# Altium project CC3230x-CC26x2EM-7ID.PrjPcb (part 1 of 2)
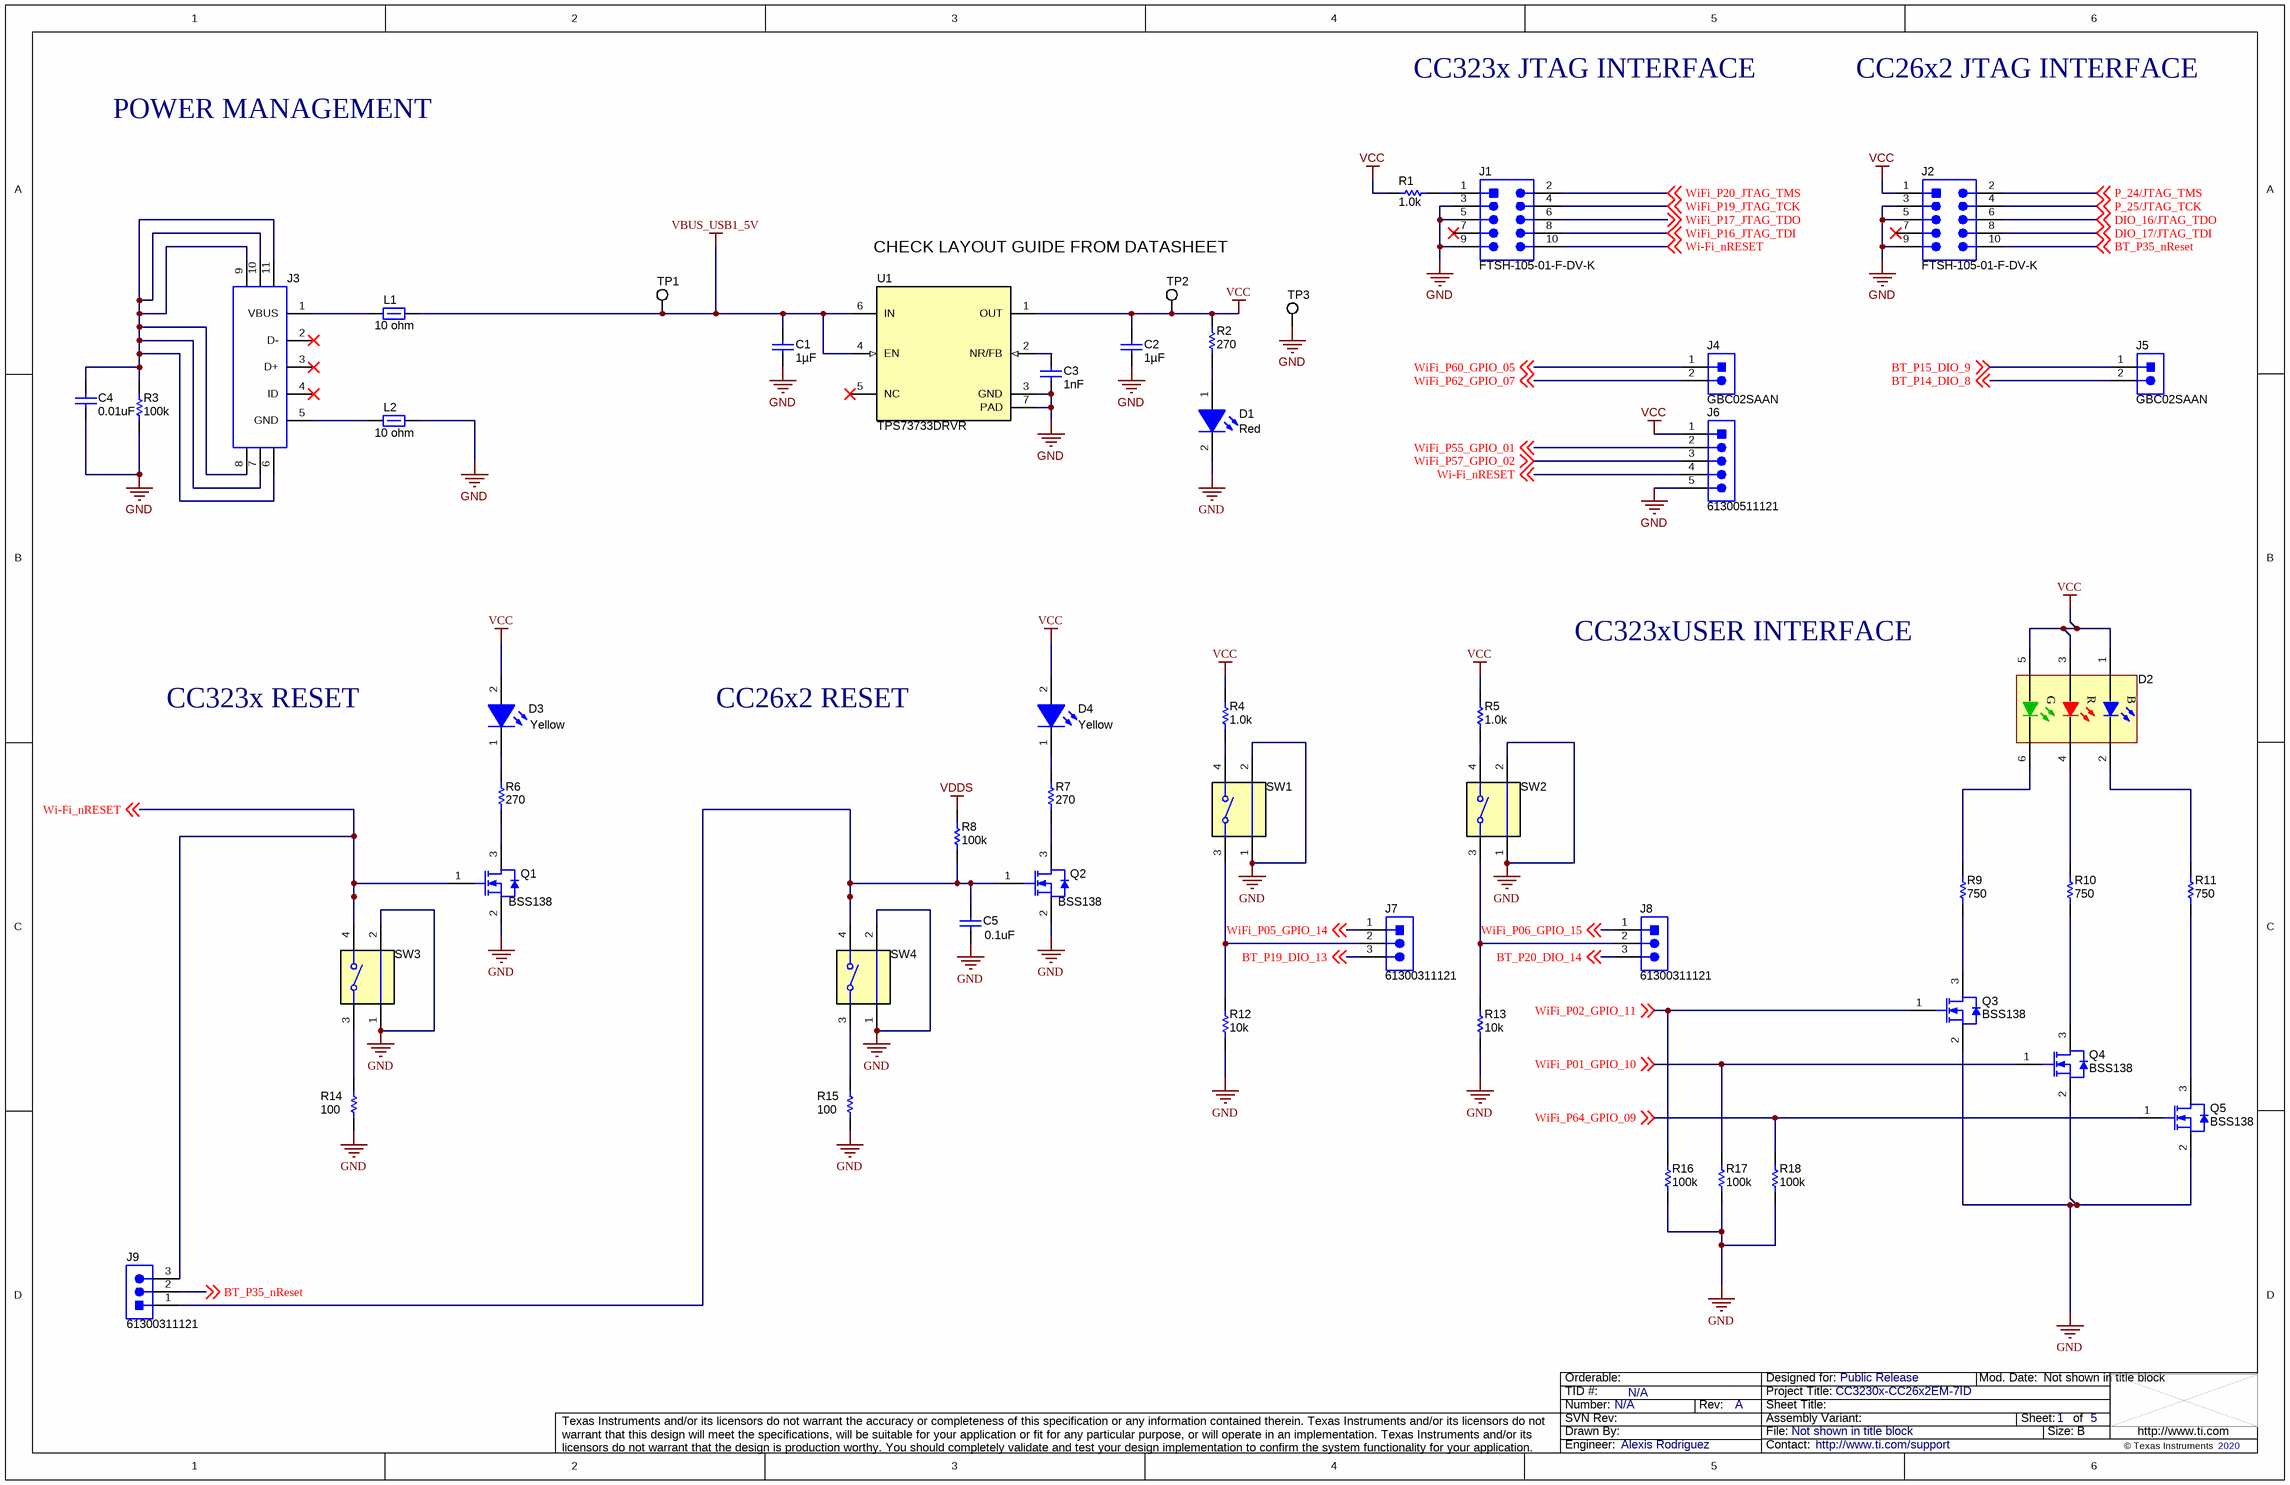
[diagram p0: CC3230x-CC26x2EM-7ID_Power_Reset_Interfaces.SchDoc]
CopyrightYear: 2020; PCB_Layout: Tessolve; PCB_Rev: A; PRJ_Customer: Public Release; PRJ_Engineer: Alexis Rodriguez; PRJ_Number: N/A; PRJ_Title: CC3230x-CC26x2EM-7ID; SCH_Rev: A; TechSupport: http://www.ti.com/support; TID: N/A
5 sheets, 160 parts. Net scope: global (net labels, ports and power ports of the same name join across sheets).
Board file: CC3230x-CC26x2EM-7ID.PcbDoc
Sheets:
  CC3230x-CC26x2EM-7ID_Power_Reset_Interfaces.SchDoc
  CC3230x-CC26x2EM-7ID_CC3230x_EngineArea.SchDoc
  CC3230x-CC26x2EM-7ID_CC26x2R_EngineArea.SchDoc
  CC3230x-CC26x2EM-7ID_AntennaRFSection.SchDoc
  CC3230x-CC26x2EM-7ID_Hardware.SchDoc

## Sheet CC3230x-CC26x2EM-7ID_Power_Reset_Interfaces.SchDoc
size 431 x 279 mm; Date: Not shown in title block; ApprovedBy: Not shown in title block; CheckedBy: Not shown in title block; Author: Not shown in title block; CompanyName: Not shown in title block; Engineer: Not shown in title block; Organization: Not shown in title block; Address1: Not shown in title block; Address2: Not shown in title block; Address3: Not shown in title block; Address4: Not shown in title block; DocumentNumber: 1; Revision: Use project parameter SCH_Rev; SheetNumber: 1; SheetTotal: 5; PageSetup: Record=PageOptions¦CenterHorizontal=True¦CenterVertical=True¦PrintScale=1.00¦XCorrection=1.00¦YCorrection=1.00¦PrintKind=0¦BorderSize=5000000¦LeftOffset=0¦BottomOffset=0¦Orientation=2¦PaperLength=1000¦PaperWidth=1000¦Scale=100¦PaperSource=15¦PrintQuality=600¦MediaType=1¦DitherType=10¦PaperKind=Letter¦PrintScaleMode=1

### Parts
C1  Cap_F: 1µF  [0603]  (hidden comment: GRM188R71E105KA12D)
C2  Cap_F: 1µF  [0603]  (hidden comment: GRM188R71E105KA12D)
C3  Cap_F: 1nF  [0603]  (hidden comment: 06031C102JAT2A)
C4  ValueDisplayed: 0.01uF  [0402]  (hidden comment: C1005X7R1C103K050BA)
C5  ValueDisplayed: 0.1uF  [0201]  (hidden comment: GRM033Z71C104KE14D)
D1  value Red  [19-217_R6C-AL1M2VY_3T_Red]  (hidden comment: 19-217/R6C-AL1M2VY/3T)
D2  EAST1616RGBA8  [EAST1616_RGB]  (value not drawn)
D3  value Yellow  [WL-SMCW_YELLOW]  (hidden comment: 150060YS75000)
D4  value Yellow  [WL-SMCW_YELLOW]  (hidden comment: 150060YS75000)
J1  FTSH-105-01-F-DV-K  [Samtec_FTSH-105-01-x-DV-K]
J2  FTSH-105-01-F-DV-K  [Samtec_FTSH-105-01-x-DV-K]
J3  1051640001  [Molex_1051640001]  (value not drawn)
J4  GBC02SAAN  [Sullins_Gxx02SAAN]
J5  GBC02SAAN  [Sullins_Gxx02SAAN]
J6  61300511121  [Wurth_61300511121]
J7  61300311121  [WURTH_61300311121]
J8  61300311121  [WURTH_61300311121]
J9  61300311121  [WURTH_61300311121]
L1  ValueDisplayed: 10 ohm  [0402]  (hidden comment: CMP-0003309-1)
L2  ValueDisplayed: 10 ohm  [0402]  (hidden comment: CMP-0003309-1)
Q1  PartNumber: BSS138  [SOT-23]  (hidden comment: CMP-0000755-1)
Q2  PartNumber: BSS138  [SOT-23]  (hidden comment: CMP-0000755-1)
Q3  BSS138  [SOT-23]
Q4  BSS138  [SOT-23]
Q5  BSS138  [SOT-23]
R1  ValueDisplayed: 1.0k  [0402]  (hidden comment: CRCW04021K00JNED)
R2  ValueDisplayed: 270  [0603]  (hidden comment: CMP-0025765-4)
R3  ValueDisplayed: 100k  [0603]  (hidden comment: CMP-0025698-4)
R4  ValueDisplayed: 1.0k  [0402]  (hidden comment: CMP-0026852-3)
R5  ValueDisplayed: 1.0k  [0402]  (hidden comment: CMP-0026852-3)
R6  ValueDisplayed: 270  [0603]  (hidden comment: CMP-0025765-4)
R7  ValueDisplayed: 270  [0603]  (hidden comment: CMP-0025765-4)
R8  ValueDisplayed: 100k  [0201]  (hidden comment: RC0201JR-7D100KL)
R9  ValueDisplayed: 750  [0603]  (hidden comment: RC0603JR-07750RL)
R10  ValueDisplayed: 750  [0603]  (hidden comment: RC0603JR-07750RL)
R11  ValueDisplayed: 750  [0603]  (hidden comment: RC0603JR-07750RL)
R12  ValueDisplayed: 10k  [0402]  (hidden comment: CMP-0026825-5)
R13  ValueDisplayed: 10k  [0402]  (hidden comment: CMP-0026825-5)
R14  ValueDisplayed: 100  [0402]  (hidden comment: CMP-0026656-1)
R15  ValueDisplayed: 100  [0402]  (hidden comment: CMP-0026656-1)
R16  ValueDisplayed: 100k  [0402]  (hidden comment: CMP-0026823-3)
R17  ValueDisplayed: 100k  [0402]  (hidden comment: CMP-0026823-3)
R18  ValueDisplayed: 100k  [0402]  (hidden comment: CMP-0026823-3)
SW1  CMP-0002328-1  [SW_1188E]  (value not drawn)
SW2  CMP-0002328-1  [SW_1188E]  (value not drawn)
SW3  CMP-0002328-1  [SW_1188E]  (value not drawn)
SW4  CMP-0002328-1  [SW_1188E]  (value not drawn)
TP1  5015  [Testpoint_Keystone_Miniature]  (value not drawn)
TP2  5015  [Testpoint_Keystone_Miniature]  (value not drawn)
TP3  5015  [Testpoint_Keystone_Miniature]  (value not drawn)
U1  TPS73733DRVR  [DRV0006A]

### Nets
GND: C1.2 C2.2 C3.2 C4.2 C5.2 D1.2(K) J1.3 J1.5 J1.9 J2.3 J2.5 J2.9 J6.5 L2.2 Q1.2(S) Q2.2(S) Q3.2(S) Q4.2(S) Q5.2(S) R3.1 R12.2 R13.2 R14.1 R15.1 R16.2 R17.2 R18.2 SW1.1 SW1.2 SW2.1 SW2.2 SW3.1 SW3.2 SW4.1 SW4.2 TP3.1 U1.3(GND) U1.7(PAD)
VBUS_USB1_5V: C1.1 L1.2 TP1.1 U1.4(EN) U1.6(IN)
VCC: C2.1 D2.1(A) D2.3(A) D2.5(A) D3.2(A) D4.2(A) J2.1 J6.1 R1.1 R2.1 R4.1 R5.1 TP2.1 U1.1(OUT)
VDDS: R8.2
BT_P14_DIO_8: J5.2 ; off-sheet BT_P14_DIO_8
BT_P15_DIO_9: J5.1 ; off-sheet BT_P15_DIO_9
BT_P19_DIO_13: J7.3 ; off-sheet BT_P19_DIO_13
BT_P20_DIO_14: J8.3 ; off-sheet BT_P20_DIO_14
BT_P35_nReset: J2.10 J9.2 ; off-sheet BT_P35_nReset
DIO_16/JTAG_TDO: J2.6 ; off-sheet DIO_16/JTAG_TDO
DIO_17/JTAG_TDI: J2.8 ; off-sheet DIO_17/JTAG_TDI
P_24/JTAG_TMS: J2.2 ; off-sheet P_24/JTAG_TMS
P_25/JTAG_TCK: J2.4 ; off-sheet P_25/JTAG_TCK
Wi-Fi_nRESET: J1.10 J6.4 J9.3 Q1.1(G) SW3.4 ; off-sheet Wi-Fi_nRESET
WiFi_P01_GPIO_10: Q4.1(G) R17.1 ; off-sheet WiFi_P01_GPIO_10
WiFi_P02_GPIO_11: Q3.1(G) R16.1 ; off-sheet WiFi_P02_GPIO_11
WiFi_P05_GPIO_14: J7.1 ; off-sheet WiFi_P05_GPIO_14
WiFi_P06_GPIO_15: J8.1 ; off-sheet WiFi_P06_GPIO_15
WiFi_P16_JTAG_TDI: J1.8 ; off-sheet WiFi_P16_JTAG_TDI
WiFi_P17_JTAG_TDO: J1.6 ; off-sheet WiFi_P17_JTAG_TDO
WiFi_P19_JTAG_TCK: J1.4 ; off-sheet WiFi_P19_JTAG_TCK
WiFi_P20_JTAG_TMS: J1.2 ; off-sheet WiFi_P20_JTAG_TMS
WiFi_P55_GPIO_01: J6.2 ; off-sheet WiFi_P55_GPIO_01
WiFi_P57_GPIO_02: J6.3 ; off-sheet WiFi_P57_GPIO_02
WiFi_P60_GPIO_05: J4.1 ; off-sheet WiFi_P60_GPIO_05
WiFi_P62_GPIO_07: J4.2 ; off-sheet WiFi_P62_GPIO_07
WiFi_P64_GPIO_09: Q5.1(G) R18.1 ; off-sheet WiFi_P64_GPIO_09
NetC3_1: C3.1 U1.2(NR/FB)
NetC4_1: C4.1 J3.6 J3.7 J3.8 J3.9 J3.10 J3.11 R3.2
NetC5_1: C5.1 J9.1 Q2.1(G) R8.1 SW4.4
NetD1_1: D1.1(A) R2.2
NetD2_2: D2.2(K) R11.2
NetD2_4: D2.4(K) R10.2
NetD2_6: D2.6(K) R9.2
NetD3_1: D3.1(K) R6.2
NetD4_1: D4.1(K) R7.2
NetJ1_1: J1.1 R1.2
NetJ3_1: J3.1(VBUS) L1.1
NetJ3_5: J3.5(GND) L2.1
NetJ7_2: J7.2 R12.1 SW1.3
NetJ8_2: J8.2 R13.1 SW2.3
NetQ1_3: Q1.3(D) R6.1
NetQ2_3: Q2.3(D) R7.1
NetQ3_3: Q3.3(D) R9.1
NetQ4_3: Q4.3(D) R10.1
NetQ5_3: Q5.3(D) R11.1
NetR4_2: R4.2 SW1.4
NetR5_2: R5.2 SW2.4
NetR14_2: R14.2 SW3.3
NetR15_2: R15.2 SW4.3

Not connected (* = marked no-connect by the designer): J1 7*; J2 7*; J3 2(D-)* 3(D+)* 4(ID)*; U1 5(NC)*

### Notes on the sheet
- CC323x JTAG INTERFACE
- CC26x2 JTAG INTERFACE
- POWER MANAGEMENT
- CHECK LAYOUT GUIDE FROM DATASHEET
- CC323xUSER INTERFACE
- CC323x RESET
- CC26x2 RESET

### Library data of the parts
C1 C2 = CMP-0007405-4: CAP, CERM, 1 uF, 25 V, +/- 10%, X7R, 0603; Manufacturer: MuRata; TaMin_C: -55°C; Polarized: N; SizeAreaWB_mm2: 4.68; Value1: Unknown; U/M: EA; Value: 1uF; TaMax_C: 125°C; SizeZ_mm: 1; SizeX_mm: 1.6; SizeY_mm: 0.8; Value2: 25V; SizeArea_mm2: 1.28; CompType: Capacitor; AEC Category: Q200
C3 = CMP-0006723-4: CAP, CERM, 1000 pF, 100 V, +/- 5%, X7R, 0603; Manufacturer: AVX; TaMin_C: -55°C; ESR_ohm: 2.76d; Polarized: N; SizeAreaWB_mm2: 4.68; Value1: 0.276 ohm; U/M: EA; Value: 1000pF; TaMax_C: 125°C; SizeZ_mm: 1; SizeX_mm: 1.6; SizeY_mm: 0.8; Value2: 100V; SizeArea_mm2: 1.28; CompType: Capacitor; AEC Category: Q200
C4 = CMP-0006292-2: CAP, CERM, 0.01 uF, 16 V, +/- 10%, X7R, 0402; Manufacturer: TDK; Alternate PartNumber: 0402B103K500CT; Alternate Manufacturer: Walsin; Polarized: N; CompType: Capacitor; Value: 0.01uF; U/M: EA; Cap_F: 10nF; ESR_ohm: 0.0623; Value1: 0.0623 ohm; VDC_V: 16V; TaMin_C: -55°C; TaMax_C: 125°C; AEC Category: Q200; SizeAreaWB_mm2: 3; SizeZ_mm: 0.6; SizeX_mm: 1; SizeY_mm: 0.5
C5 = CMP-0064970-1: CAP, CERM, 0.1 uF, 16 V,+/- 10%, X7R, 0201; Manufacturer: MuRata; TaMin_C: -55°C; Polarized: N; SizeAreaWB_mm2: 2.08; Value1: Unknown; U/M: EA; Value: 0.1uF; TaMax_C: 125°C; SizeZ_mm: 0.26; SizeX_mm: 0.6; SizeY_mm: 0.3; Value2: 16V; SizeArea_mm2: 0.18; CompType: Capacitor; Cap_F: 100nF; AEC Category: Q200
D1 = CMP-0086159-1: LED, Red, SMD; Manufacturer: Everlight; SizeArea_mm2: 1.28; Tjmax_C: 85°C; Angle: 120; SizeZ_mm: 0.5; Value1: 0.06W; Ir_A: 10µA; SizeX_mm: 1.6; Io_A: 5mA; Vf_V: 1.95V; SizeY_mm: 0.8; Vr_V: 5V; Power_TotalModule: 60mW; SizeAreaWB_mm2: 4.68
D2 = CMP-0003017-3: LED, RGB, SMD; Manufacturer: Everlight; SizeZ_mm: 0.45; Io_A: 25mA; SizeY_mm: 1.6; Type: InGaN; Ir_A: 50µA; Vr_V: 5V; Value2: 3.7V; SizeAreaWB_mm2: 6.76; SizeArea_mm2: 2.56; Angle: 120; Tjmax_C: 85°C
D3 D4 = CMP-0002892-3: LED, Yellow, SMD; Manufacturer: Wurth Elektronik; Value1: W; Vf_V: 2V; Type: AlInGaP; Io_A: 20mA
J1 J2 = CMP-0075670-2: Header (Shrouded), 1.27mm, 5x2, Gold, SMT; Manufacturer: Samtec; Pitch_mm: 1.27; Gender: Male; Cert_CSA: Y; Current_A: 3.3A; Row_Count: 2
J3 = CMP-0055311-1: Receptacle, USB 2.0, Micro B, 5 Position, R/A, SMT; Manufacturer: Molex; CNHeader: FALSE; Current_A: 1.8A; Gender: Female; Voltage_V: 30V; Pitch_mm: 0.65; ContactFinish: Gold; CT: TRUE; Cert_UL: Y
J4 J5 = CMP-0054576-1: Header, 2.54 mm, 2x1, Gold, TH; Manufacturer: Sullins Connector Solutions; CT: FALSE; CNHeader: TRUE
J6 = CMP-0084909-1: Header, 2.54mm, 5x1, Gold, TH; Manufacturer: Wurth Elektronik; Pitch_mm: 2.54; Gender: Male; Row_Count: 1; Shrouded: N; Current_A: 3A; Voltage_V: 250V
J7-J9 = CMP-0054796-2: Header, 2.54 mm, 3x1, Gold, TH; Manufacturer: Wurth Elektronik; Pitch_mm: 2.54; Green_Lifecycle: Active; Cert_UL: Y; Shrouded: N; Green_REACh: Passed; Gender: Male; Row_Count: 1
L1 L2 = CMP-0003309-1: Ferrite Bead, 10 ohm @ 100 MHz, 1 A, 0402; PartNumber: BLM15AG100SN1D; Manufacturer: MuRata; Alternate PartNumber: ----; Value: 10 ohm; Imax_A: 1A; DCR_ohm: 0.025; Value1: 0.025 ohm; ZTyp@100MHz_Ohm: 10; SizeAreaWB_mm2: 3; SizeZ_mm: 0.6; SizeX_mm: 1; SizeY_mm: 0.5
Q1 Q2 = CMP-0000755-1: MOSFET, N-CH, 50 V, 0.22 A, SOT-23; Manufacturer: Fairchild Semiconductor; Alternate Manufacturer: ON; Alternate PartNumber: BSS138LT1G; U/M: EA; ChType: N; Value: 50V; Rdson45_ohm: 6; Value2: 1.7 nC; QgTyp_nC: 1.7; Vgs_V: 20V; IdsMax_A: 2.2dA; SizeZ_mm: 1.1; SizeX_mm: 2.5; SizeY_mm: 3; SizeArea_mm2: 7.5; AEC Category: Q101; SizeAreaWB_mm2: 14
Q3-Q5 = CMP-0000755-1: MOSFET, N-CH, 50 V, 0.22 A, SOT-23; Alternate Manufacturer: None; Manufacturer: Fairchild Semiconductor; SizeZ_mm: 1.1; ChType: N; Value2: 1.7 nC; VdsMax_V: 50V; SizeX_mm: 2.5; SizeY_mm: 3; Vgs_V: 20V; Value: 50V; Rdson45_ohm: 6; SizeArea_mm2: 7.5; AEC Category: Q101; IdsMax_A: 2.2dA; SizeAreaWB_mm2: 14; U/M: EA; QgTyp_nC: 1.7
R1 = CMP-0026852-3: RES, 1.0 k, 5%, 0.063 W, AEC-Q200 Grade 0, 0402; Manufacturer: Vishay-Dale; Power_W: 63mW; TempCo: 200 ppm/C; Value_Code: 1k00; Value: 1.0k; EIA_Code: E24; Res_ohm: 1k; SizeX_mm: 1; SizeY_mm: 0.5; SizeZ_mm: 0.6; Value2: 0.063W; AEC Qualified: Y; VDC_V: 50V; AEC Category: Q200; AEC Grade: 0
R2 = CMP-0025765-4: RES, 270, 5%, 0.1 W, AEC-Q200 Grade 0, 0603; PartNumber: CRCW0603270RJNEA; Manufacturer: Vishay-Dale; Alternate Manufacturer: YAGEO; Alternate PartNumber: RC0603JR-07270RL; Value: 270; Value_Code: 270R; Power_W: 100mW; Value2: 0.1W; VDC_V: 75V; TempCo: 200 ppm/C; EIA_Code: E24; SizeX_mm: 1.6; SizeY_mm: 0.8; SizeZ_mm: 1; SizeArea_mm2: 1.28; AEC Qualified: Y; AEC Category: Q200; AEC Grade: 0
R3 = CMP-0025698-4: RES, 100 k, 5%, 0.1 W, AEC-Q200 Grade 0, 0603; PartNumber: CRCW0603100KJNEA; Manufacturer: Vishay-Dale; Alternate Manufacturer: YAGEO; Alternate PartNumber: RC0603JR-07100KL; CompType: Resistor; Value: 100k; Power_W: 100mW; Value2: 0.1W; VDC_V: 75V; TempCo: 200 ppm/C; EIA_Code: E24; AEC Category: Q200; AEC Qualified: Y; AEC Grade: 0; SizeX_mm: 1.6; SizeY_mm: 0.8; SizeZ_mm: 1; SizeArea_mm2: 1.28
R4 R5 = CMP-0026852-3: RES, 1.0 k, 5%, 0.063 W, AEC-Q200 Grade 0, 0402; PartNumber: CRCW04021K00JNED; Manufacturer: Vishay-Dale; Alternate Manufacturer: YAGEO; Alternate PartNumber: RC0402JR-071KL; Value: 1.0k; Res_ohm: 1k; Value_Code: 1k00; Power_W: 63mW; Value2: 0.063W; VDC_V: 50V; TempCo: 200 ppm/C; EIA_Code: E24; SizeX_mm: 1; SizeY_mm: 0.5; SizeZ_mm: 0.6; AEC Qualified: Y; AEC Category: Q200; AEC Grade: 0
R6 R7 = CMP-0025765-4: RES, 270, 5%, 0.1 W, AEC-Q200 Grade 0, 0603; PartNumber: CRCW0603270RJNEA; Manufacturer: Vishay-Dale; Alternate Manufacturer: YAGEO; Alternate PartNumber: RC0603JR-07270RL; CompType: Resistor; Value: 270; Value_Code: 270R; Power_W: 100mW; Value2: 0.1W; VDC_V: 75V; TempCo: 200 ppm/C; EIA_Code: E24; SizeX_mm: 1.6; SizeY_mm: 0.8; SizeZ_mm: 1; SizeArea_mm2: 1.28; AEC Qualified: Y; AEC Category: Q200; AEC Grade: 0
R8 = CMP-0027184-1: RES, 100 k, 5%, 0.05 W, 0201; Manufacturer: Yageo America; Power_W: 50mW; TempCo: 200 ppm/C; U/M: EA; Value: 100k; EIA_Code: E24; SizeX_mm: 0.6; SizeY_mm: 0.3; SizeZ_mm: 0.26; Value2: 0.05W; SizeArea_mm2: 0.18; CompType: Resistor; AEC Qualified: N; VDC_V: 25V; AEC Category: Q200
R9-R11 = CMP-0025939-5: RES, 750, 5%, 0.1 W, 0603; Manufacturer: Yageo; Power_W: 100mW; TempCo: 100 ppm/C; Value_Code: 750R; Value: 750; EIA_Code: E24; SizeX_mm: 1.6; SizeY_mm: 0.8; SizeZ_mm: 1; Value2: 0.1W; SizeArea_mm2: 1.28; AEC Qualified: N; VDC_V: 75V; AEC Category: Q200; SizeAreaWB_mm2: 4.68
R12 R13 = CMP-0026825-5: RES, 10 k, 5%, 0.063 W, AEC-Q200 Grade 0, 0402; PartNumber: CRCW040210K0JNED; Manufacturer: Vishay-Dale; Alternate Manufacturer: YAGEO; Alternate PartNumber: RC0402JR-0710KL; Value: 10k; Value_Code: 10k0; Power_W: 63mW; Value2: 0.063W; VDC_V: 50V; TempCo: 200 ppm/C; EIA_Code: E24; SizeX_mm: 1; SizeY_mm: 0.5; SizeZ_mm: 0.6; AEC Qualified: Y; AEC Category: Q200; AEC Grade: 0
R14 R15 = CMP-0026656-1: RES, 100, 1%, 0.1 W, 0402; PartNumber: ERJ-2RKF1000X; Manufacturer: Panasonic; Alternate Manufacturer: YAGEO; Alternate PartNumber: RC0402FR-07100RL; CompType: Resistor; Value: 100; Value_Code: 100R; Power_W: 100mW; Value2: 0.1W; VDC_V: 50V; TempCo: 100 ppm/C; EIA_Code: E96; U/M: EA; SizeX_mm: 1; SizeY_mm: 0.5; SizeZ_mm: 0.6; AEC Category: Q200
R16-R18 = CMP-0026823-3: RES, 100 k, 5%, 0.063 W, AEC-Q200 Grade 0, 0402; PartNumber: CRCW0402100KJNED; Manufacturer: Vishay-Dale; Alternate Manufacturer: YAGEO; Alternate PartNumber: RC0402JR-07100KL; Value: 100k; Power_W: 63mW; Value2: 0.063W; VDC_V: 50V; TempCo: 200 ppm/C; EIA_Code: E24; SizeArea_mm2: 0.5; SizeX_mm: 1; SizeZ_mm: 0.6; AEC Category: Q200; AEC Qualified: Y; AEC Grade: 0
SW1-SW4 = CMP-0002328-1: Switch, SPST, 0.05 A, 12 VDC, SMD; PartNumber: 1188E-1K2-V-TR; Manufacturer: Diptronics; Alternate Manufacturer: ----; VDC_V: 12V; PositionCount: 1; CurrentRating_mA: 50A; SizeAreaWB_mm2: 53.9; SizeArea_mm2: 27.3; SizeX_mm: 7.8; SizeY_mm: 3.5
TP1-TP3 = CMP-0055152-1: Test Point, Miniature, SMT; Manufacturer: Keystone; CNHeader: FALSE; Green_Lifecycle: Active; Green_REACh: Passed; CT: TRUE
U1 = CMP-0073832-5: Single Output LDO, 1A, Adj. (1.2 to 5.0V), Reverse Current Protection, DRV0006A (WSON-6); Manufacturer: Texas Instruments; Alternate PartNumber: TPS73733DRVT; SizeX_mm: 2; CompType: IC; SizeZ_mm: 0.8; SizeArea_mm2: 4; SizeAreaWB_mm2: 9; Green_Lifecycle: Active; Green_REACh: Passed; AEC Category: Q200; AEC Qualified: N; Rating: Catalog

## Sheet CC3230x-CC26x2EM-7ID_CC3230x_EngineArea.SchDoc
size 558 x 431 mm; Date: Not shown in title block; ApprovedBy: Not shown in title block; CheckedBy: Not shown in title block; Author: Not shown in title block; CompanyName: Not shown in title block; Engineer: Not shown in title block; Organization: Not shown in title block; Address1: Not shown in title block; Address2: Not shown in title block; Address3: Not shown in title block; Address4: Not shown in title block; DocumentNumber: 2; Revision: Use project parameter SCH_Rev; SheetNumber: 2; SheetTotal: 5; PageSetup: Record=PageOptions¦CenterHorizontal=True¦CenterVertical=True¦PrintScale=1.00¦XCorrection=1.00¦YCorrection=1.00¦PrintKind=0¦BorderSize=5000000¦LeftOffset=0¦BottomOffset=0¦Orientation=2¦PaperLength=1000¦PaperWidth=1000¦Scale=100¦PaperSource=15¦PrintQuality=600¦MediaType=1¦DitherType=10¦PaperKind=Letter¦PrintScaleMode=1
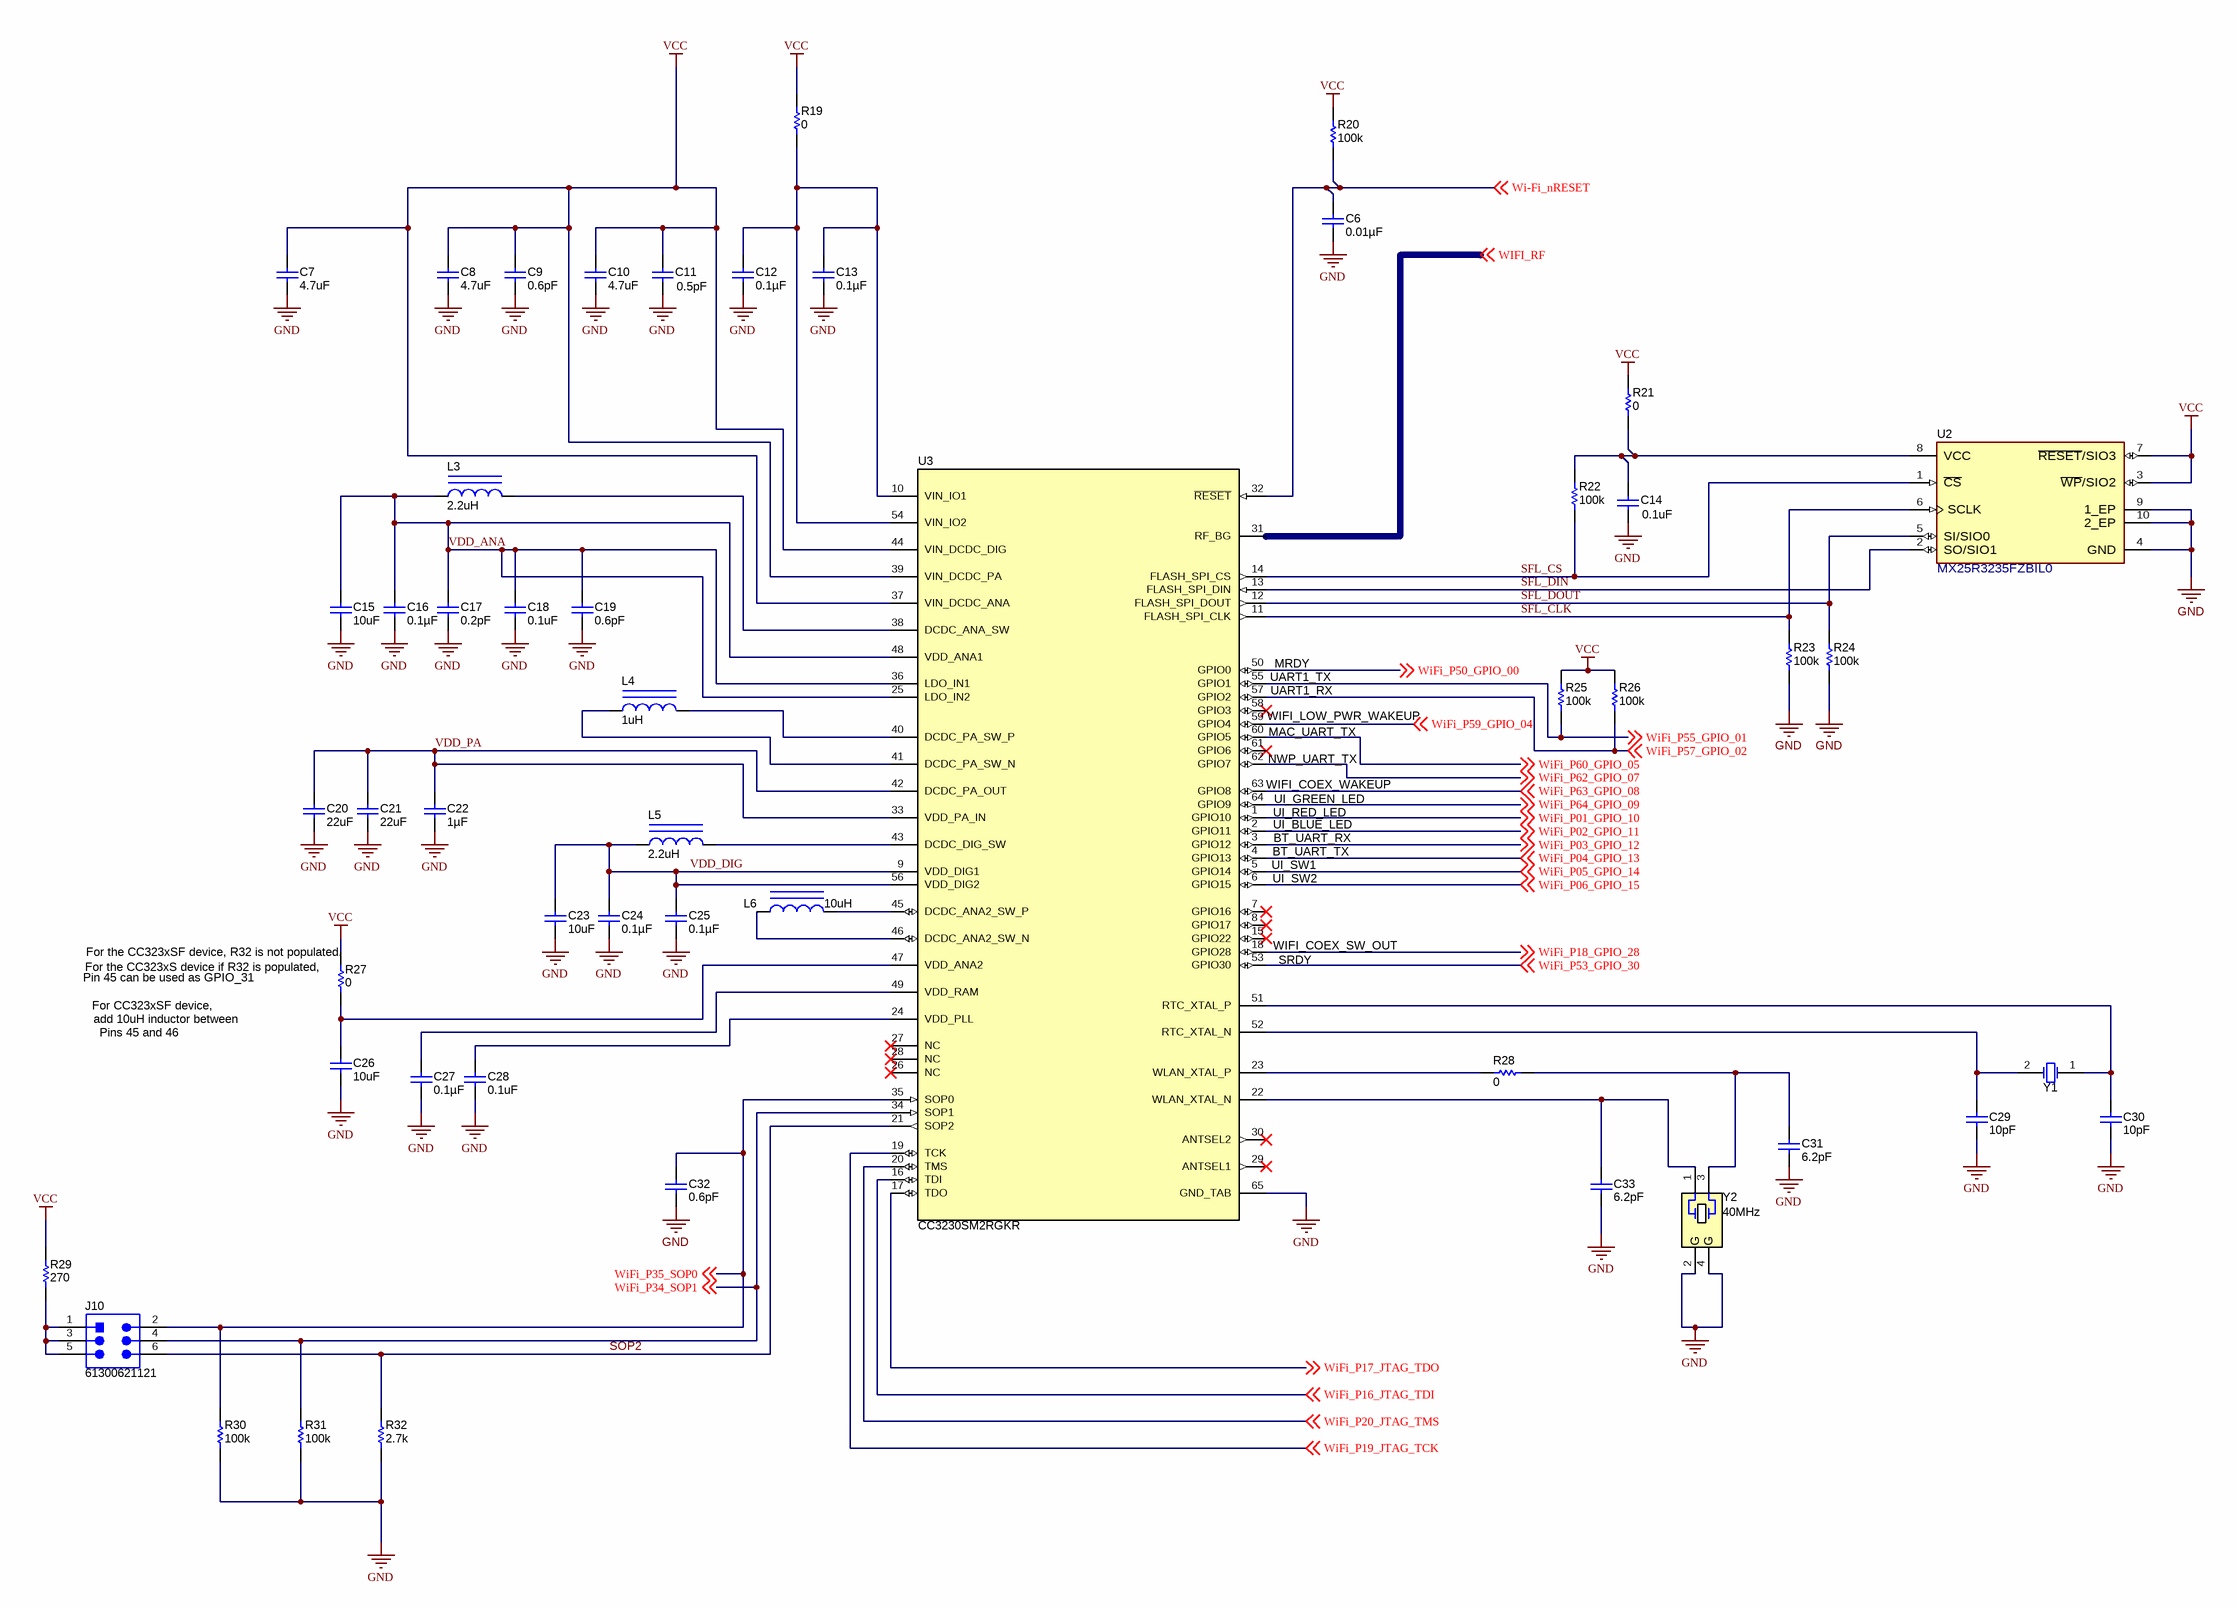
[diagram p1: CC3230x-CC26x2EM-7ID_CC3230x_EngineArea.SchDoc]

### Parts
C6  ValueDisplayed: 0.01µF  [0402S]  (hidden comment: 0402B103K500CT)
C7  ValueDisplayed: 4.7uF  [0402]  (hidden comment: CMP-0064972-2)
C8  ValueDisplayed: 4.7uF  [0402]  (hidden comment: CMP-0064972-2)
C9  ValueDisplayed: 0.6pF  [0201_033]  (hidden comment: GJM0335C1ER60BB01D)
C10  ValueDisplayed: 4.7uF  [0402]  (hidden comment: CMP-0064972-2)
C11  ValueDisplayed: 0.5pF  [0201_033]  (hidden comment: GJM0335C1ER50BB01D)
C12  ValueDisplayed: 0.1µF  [0402S]  (hidden comment: CL05B104KO5NNNC)
C13  ValueDisplayed: 0.1µF  [0402S]  (hidden comment: CL05B104KO5NNNC)
C14  ValueDisplayed: 0.1uF  [0201]  (hidden comment: GRM033Z71C104KE14D)
C15  ValueDisplayed: 10uF  [0603]  (hidden comment: CMP-0064953-4)
C16  ValueDisplayed: 0.1µF  [0402S]  (hidden comment: CL05B104KO5NNNC)
C17  ValueDisplayed: 0.2pF  [0201_033]  (hidden comment: GJM0335C1ER20BB01D)
C18  ValueDisplayed: 0.1uF  [0201]  (hidden comment: CL03A104KP3NNNC)
C19  ValueDisplayed: 0.6pF  [0201_033]  (hidden comment: GJM0335C1ER60BB01D)
C20  ValueDisplayed: 22uF  [0603]  (hidden comment: CMP-0064952-4)
C21  ValueDisplayed: 22uF  [0603]  (hidden comment: CMP-0064952-4)
C22  ValueDisplayed: 1µF  [0402S]  (hidden comment: CL05A105MP5NNNC)
C23  ValueDisplayed: 10uF  [0603]  (hidden comment: CMP-0064953-4)
C24  ValueDisplayed: 0.1µF  [0402S]  (hidden comment: CL05B104KO5NNNC)
C25  ValueDisplayed: 0.1µF  [0402S]  (hidden comment: CL05B104KO5NNNC)
C26  ValueDisplayed: 10uF  [0603]  (hidden comment: CMP-0064953-4)
C27  ValueDisplayed: 0.1µF  [0402S]  (hidden comment: CL05B104KO5NNNC)
C28  ValueDisplayed: 0.1uF  [0201]  (hidden comment: CMP-0009655-3)
C29  ValueDisplayed: 10pF  [0402S]  (hidden comment: 0402N100J500CT)
C30  ValueDisplayed: 10pF  [0402S]  (hidden comment: 0402N100J500CT)
C31  ValueDisplayed: 6.2pF  [0402S]  (hidden comment: 0402N6R2C500CT)
C32  ValueDisplayed: 0.6pF  [0201_033]  (hidden comment: GJM0335C1ER60BB01D)
C33  ValueDisplayed: 6.2pF  [0402S]  (hidden comment: 0402N6R2C500CT)
J10  61300621121  [Wurth_61300621121]
L3  ValueDisplayed: 2.2uH  [LQM2MPN_G0]  (hidden comment: CMP-0058761-1)
L4  ValueDisplayed: 1uH  [1008]  (hidden comment: CMP-0058750-1)
L5  ValueDisplayed: 2.2uH  [LQM2MPN_G0]  (hidden comment: CMP-0058761-1)
L6  ValueDisplayed: 10uH  [MLP2520S-M]  (hidden comment: CMP-0062710-1)
R19  ValueDisplayed: 0  [0201]  (hidden comment: CRCW02010000Z0ED)
R20  ValueDisplayed: 100k  [0402]  (hidden comment: CRCW0402100KJNED)
R21  ValueDisplayed: 0  [0201]  (hidden comment: CRCW02010000Z0ED)
R22  ValueDisplayed: 100k  [0201]  (hidden comment: RC0201JR-7D100KL)
R23  ValueDisplayed: 100k  [0201]  (hidden comment: RC0201JR-7D100KL)
R24  ValueDisplayed: 100k  [0201]  (hidden comment: RC0201JR-7D100KL)
R25  ValueDisplayed: 100k  [0201]  (hidden comment: RC0201JR-7D100KL)
R26  ValueDisplayed: 100k  [0201]  (hidden comment: RC0201JR-7D100KL)
R27  ValueDisplayed: 0  [0201]  (hidden comment: CRCW02010000Z0ED)
R28  ValueDisplayed: 0  [0201]  (hidden comment: CRCW02010000Z0ED)
R29  ValueDisplayed: 270  [0402]  (hidden comment: CRCW0402270RJNED)
R30  ValueDisplayed: 100k  [0402]  (hidden comment: CRCW0402100KJNED)
R31  ValueDisplayed: 100k  [0402]  (hidden comment: CRCW0402100KJNED)
R32  ValueDisplayed: 2.7k  [0402]  (hidden comment: CRCW04022K70JNED)
U2  MX25R3235FZBIL0  [FP-MX25R3235FZBIL0_USON8-MFG]
U3  CC3230SM2RGKR  [RGK0064B]
Y1  CMP-0004575-3  [XTAL_ABS07]  (value not drawn)
Y2  Frequency_Fixed: 40MHz  [TXC_8Y]  (hidden comment: 8Y40072002)

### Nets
GND: C6.2 C7.2 C8.2 C9.2 C10.2 C11.2 C12.2 C13.2 C14.2 C15.2 C16.2 C17.2 C18.2 C19.2 C20.2 C21.2 C22.2 C23.2 C24.2 C25.2 C26.2 C27.2 C28.2 C29.2 C30.2 C31.2 C32.2 C33.2 R23.1 R24.1 R30.1 R31.1 R32.1 U2.4(GND) U2.9(1_EP) U2.10(2_EP) U3.65(GND_TAB) Y2.2(GND) Y2.4(GND)
VCC: C7.1 C8.1 C9.1 C10.1 C11.1 R19.2 R20.2 R21.2 R25.2 R26.2 R27.2 R29.2 U2.3(~{WP}/SIO2) U2.7(~{RESET}/SIO3) U3.37(VIN_DCDC_ANA) U3.39(VIN_DCDC_PA) U3.44(VIN_DCDC_DIG)
SFL_CLK: R23.2 U2.6(SCLK) U3.11(FLASH_SPI_CLK)
SFL_CS: R22.1 U2.1(~{CS}) U3.14(FLASH_SPI_CS)
SFL_DIN: U2.2(SO/SIO1) U3.13(FLASH_SPI_DIN)
SFL_DOUT: R24.2 U2.5(SI/SIO0) U3.12(FLASH_SPI_DOUT)
SOP2: J10.6 R32.2 U3.21(SOP2)
VDD_ANA: C15.1 C16.1 C17.1 C18.1 C19.1 L3.1 U3.25(LDO_IN2) U3.36(LDO_IN1) U3.48(VDD_ANA1)
VDD_DIG: C23.1 C24.1 C25.1 L5.1 U3.9(VDD_DIG1) U3.56(VDD_DIG2)
VDD_PA: C20.1 C21.1 C22.1 U3.33(VDD_PA_IN) U3.42(DCDC_PA_OUT)
Wi-Fi_nRESET: C6.1 R20.1 U3.32(~{RESET}) ; off-sheet Wi-Fi_nRESET
WiFi_P01_GPIO_10: U3.1(GPIO10) ; off-sheet WiFi_P01_GPIO_10
WiFi_P02_GPIO_11: U3.2(GPIO11) ; off-sheet WiFi_P02_GPIO_11
WiFi_P03_GPIO_12: U3.3(GPIO12) ; off-sheet WiFi_P03_GPIO_12
WiFi_P04_GPIO_13: U3.4(GPIO13) ; off-sheet WiFi_P04_GPIO_13
WiFi_P05_GPIO_14: U3.5(GPIO14) ; off-sheet WiFi_P05_GPIO_14
WiFi_P06_GPIO_15: U3.6(GPIO15) ; off-sheet WiFi_P06_GPIO_15
WiFi_P16_JTAG_TDI: U3.16(TDI) ; off-sheet WiFi_P16_JTAG_TDI
WiFi_P17_JTAG_TDO: U3.17(TDO) ; off-sheet WiFi_P17_JTAG_TDO
WiFi_P18_GPIO_28: U3.18(GPIO28) ; off-sheet WiFi_P18_GPIO_28
WiFi_P19_JTAG_TCK: U3.19(TCK) ; off-sheet WiFi_P19_JTAG_TCK
WiFi_P20_JTAG_TMS: U3.20(TMS) ; off-sheet WiFi_P20_JTAG_TMS
WiFi_P34_SOP1: J10.4 R31.2 U3.34(SOP1) ; off-sheet WiFi_P34_SOP1
WiFi_P35_SOP0: C32.1 J10.2 R30.2 U3.35(SOP0) ; off-sheet WiFi_P35_SOP0
WiFi_P50_GPIO_00: U3.50(GPIO0) ; off-sheet WiFi_P50_GPIO_00
WiFi_P53_GPIO_30: U3.53(GPIO30) ; off-sheet WiFi_P53_GPIO_30
WiFi_P55_GPIO_01: R25.1 U3.55(GPIO1) ; off-sheet WiFi_P55_GPIO_01
WiFi_P57_GPIO_02: R26.1 U3.57(GPIO2) ; off-sheet WiFi_P57_GPIO_02
WiFi_P59_GPIO_04: U3.59(GPIO4) ; off-sheet WiFi_P59_GPIO_04
WiFi_P60_GPIO_05: U3.60(GPIO5) ; off-sheet WiFi_P60_GPIO_05
WiFi_P62_GPIO_07: U3.62(GPIO7) ; off-sheet WiFi_P62_GPIO_07
WiFi_P63_GPIO_08: U3.63(GPIO8) ; off-sheet WiFi_P63_GPIO_08
WiFi_P64_GPIO_09: U3.64(GPIO9) ; off-sheet WiFi_P64_GPIO_09
WIFI_RF: U3.31(RF_BG) ; off-sheet WIFI_RF
NetC12_1: C12.1 C13.1 R19.1 U3.10(VIN_IO1) U3.54(VIN_IO2)
NetC14_1: C14.1 R21.1 R22.2 U2.8(VCC)
NetC26_1: C26.1 R27.1 U3.47(VDD_ANA2)
NetC27_1: C27.1 U3.49(VDD_RAM)
NetC28_1: C28.1 U3.24(VDD_PLL)
NetC29_1: C29.1 U3.52(RTC_XTAL_N) Y1.2(OSC2)
NetC30_1: C30.1 U3.51(RTC_XTAL_P) Y1.1(OSC1)
NetC31_1: C31.1 R28.1 Y2.3
NetC33_1: C33.1 U3.22(WLAN_XTAL_N) Y2.1
NetJ10_1: J10.1 J10.3 J10.5 R29.1
NetL3_2: L3.2 U3.38(DCDC_ANA_SW)
NetL4_1: L4.1 U3.41(DCDC_PA_SW_N)
NetL4_2: L4.2 U3.40(DCDC_PA_SW_P)
NetL5_2: L5.2 U3.43(DCDC_DIG_SW)
NetL6_1: L6.1 U3.46(DCDC_ANA2_SW_N)
NetL6_2: L6.2 U3.45(DCDC_ANA2_SW_P)
NetR28_2: R28.2 U3.23(WLAN_XTAL_P)

Not connected (* = marked no-connect by the designer): U3 7(GPIO16)* 8(GPIO17)* 15(GPIO22)* 26(NC)* 27(NC)* 28(NC)* 29(ANTSEL1)* 30(ANTSEL2)* 58(GPIO3)* 61(GPIO6)*

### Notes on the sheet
- (near U3) MRDY
- (near U3) UART1_TX
- (near U3) UART1_RX
- (near U3) MAC_UART_TX
- (near U3) WIFI_LOW_PWR_WAKEUP
- (near U3) NWP_UART_TX
- (near U3) UI_GREEN_LED
- (near U3) WIFI_COEX_WAKEUP
- (near U3) UI_SW1
- (near U3) UI_RED_LED
- (near U3) BT_UART_TX
- (near U3) UI_BLUE_LED
- (near U3) BT_UART_RX
- (near U3) UI_SW2
- (near U3) WIFI_COEX_SW_OUT
- For CC323xSF device,
- Pin 45 can be used as GPIO_31
- (near R27) For the CC323xS device if R32 is populated,
- (near R27) For the CC323xSF device, R32 is not populated.
- (near U3) SRDY
- Pins 45 and 46
- add 10uH inductor between

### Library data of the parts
C6 = CMP-0085842-1: CAP, CERM, 0.01 µF, 50 V,+/- 10%, X7R, 0402; Manufacturer: Walsin; Alternate PartNumber: GRM155R71E103KA01D; Polarized: N; Value: 0.01uF; U/M: EA; Cap_F: 10nF; VDC_V: 50V; TaMin_C: -55°C; TaMax_C: 125°C; Cap_Case: 0402; SizeArea_mm2: 0.5; SizeAreaWB_mm2: 3; SizeX_mm: 1; SizeZ_mm: 0.6; AEC Category: Q200
C7 C8 C10 = CMP-0064972-2: CAP, CERM, 4.7 uF, 6.3 V,+/- 20%, X6S, 0402; PartNumber: JMK105BC6475MV-F; Manufacturer: Taiyo Yuden; Alternate PartNumber: CL05A475MQ5NRNC; Alternate Manufacturer: SAMSUNG; Polarized: N; CompType: Capacitor; Value: 4.7uF; U/M: EA; Cap_F: 4.7µF; Value1: Unknown; VDC_V: 6.3V; TaMin_C: -55°C; TaMax_C: 105°C; SizeArea_mm2: 0.5; SizeAreaWB_mm2: 3; SizeX_mm: 1; SizeZ_mm: 0.6; AEC Category: Q200
C9 C19 = CMP-0085407-1: CAP, CERM, 0.6pF, 25 V,+/- 16%, C0G/NP0, 0201; Manufacturer: MuRata; Polarized: N; U/M: EA; VDC_V: 25V; TaMin_C: -55°C; TaMax_C: 125°C; Cap_Case: 0201; SizeArea_mm2: 0.18; SizeAreaWB_mm2: 2.08; SizeX_mm: 0.6; SizeY_mm: 0.3; SizeZ_mm: 0.33; AEC Category: Q200
C11 = CMP-0085408-2: CAP, CERM, 0.5 pF, 25 V,+/- 20%, C0G/NP0, 0201; Manufacturer: MuRata; U/M: EA; SizeX_mm: 0.6; AEC Category: Q200; Cap_Case: 0201; TaMax_C: 125°C; SizeArea_mm2: 0.18; SizeAreaWB_mm2: 2.08; CompType: Capacitor; SizeY_mm: 0.3; TaMin_C: -55°C; SizeZ_mm: 0.33; AEC Qualified: N; VDC_V: 25V; Value: 0.5pF
C12 C13 C16 C24 C25 C27 = CMP-0085850-1: CAP, CERM, 0.1 µF, 16 V,+/- 10%, X7R, 0402; Manufacturer: Walsin; Alternate PartNumber: C1005X5R1A104K050BA; Polarized: N; Value: 0.1uF; U/M: EA; Cap_F: 100nF; VDC_V: 16V; TaMin_C: -55°C; TaMax_C: 125°C; Cap_Case: 0402; SizeArea_mm2: 0.5; SizeAreaWB_mm2: 3; SizeX_mm: 1; SizeZ_mm: 0.6; AEC Category: Q200
C14 = CMP-0064970-1: as C5 on sheet CC3230x-CC26x2EM-7ID_Power_Reset_Interfaces
C15 C23 C26 = CMP-0064953-4: CAP, CERM, 10 uF, 10 V,+/- 20%, X6S, 0603; PartNumber: LMK107BC6106MA-T; Manufacturer: Taiyo Yuden; Alternate PartNumber: CL10A106MP8NNNC; Alternate Manufacturer: SAMSUNG; Polarized: N; CompType: Capacitor; Value: 10uF; U/M: EA; Cap_F: 10µF; Value1: Unknown; VDC_V: 10V; TaMin_C: -55°C; TaMax_C: 105°C; SizeArea_mm2: 1.28; SizeAreaWB_mm2: 4.68; SizeX_mm: 1.6; SizeY_mm: 0.8; SizeZ_mm: 1; AEC Category: Q200
C17 = CMP-0085602-1: CAP, CERM, 0.2pF, 25 V,+/- 50%, C0G/NP0, 0201; Manufacturer: MuRata; Polarized: N; U/M: EA; VDC_V: 25V; TaMin_C: -55°C; TaMax_C: 125°C; Cap_Case: 0201; SizeArea_mm2: 0.18; SizeAreaWB_mm2: 2.08; SizeX_mm: 0.6; SizeY_mm: 0.3; SizeZ_mm: 0.33; AEC Category: Q200
C18 = CMP-0009655-3: CAP, CERM, 0.1 uF, 10 V, +/- 10%, X5R, 0201; Manufacturer: Samsung Electro-Mechanics; Polarized: N; Value: 0.1uF; U/M: EA; Cap_F: 100nF; Value1: Unknown; VDC_V: 10V; TaMin_C: -55°C; TaMax_C: 85°C; SizeArea_mm2: 0.18; SizeAreaWB_mm2: 2.08; SizeX_mm: 0.6; SizeY_mm: 0.3; SizeZ_mm: 0.26; AEC Category: Q200
C20 C21 = CMP-0064952-4: CAP, CERM, 22 uF, 4 V,+/- 20%, X6S, 0603; PartNumber: GRM188C80G226ME15J; Manufacturer: MuRata; Alternate PartNumber: CL10A226MQ8NRNC; Alternate Manufacturer: SAMSUNG; Polarized: N; CompType: Capacitor; Value: 22uF; U/M: EA; Cap_F: 22µF; Value1: Unknown; VDC_V: 4V; TaMin_C: -55°C; TaMax_C: 105°C; SizeArea_mm2: 1.28; SizeAreaWB_mm2: 4.68; SizeX_mm: 1.6; SizeY_mm: 0.8; SizeZ_mm: 1; AEC Category: Q200
C22 = CMP-0085849-1: CAP, CERM, 1 µF, 10 V,+/- 20%, X5R, 0402; Manufacturer: Walsin; Alternate PartNumber: GRM155C81A105KA12D; Polarized: N; Value: 1uF; U/M: EA; VDC_V: 10V; TaMin_C: -55°C; TaMax_C: 85°C; Cap_Case: 0402; SizeArea_mm2: 0.5; SizeAreaWB_mm2: 3; SizeX_mm: 1; SizeZ_mm: 0.6; AEC Category: Q200
C28 = CMP-0009655-3: CAP, CERM, 0.1 uF, 10 V, +/- 10%, X5R, 0201; PartNumber: CL03A104KP3NNNC; Manufacturer: Samsung Electro-Mechanics; Polarized: N; Value: 0.1uF; U/M: EA; Cap_F: 100nF; Value1: Unknown; VDC_V: 10V; TaMin_C: -55°C; TaMax_C: 85°C; SizeArea_mm2: 0.18; SizeAreaWB_mm2: 2.08; SizeX_mm: 0.6; SizeY_mm: 0.3; SizeZ_mm: 0.26; AEC Category: Q200
C29 C30 = CMP-0085843-1: CAP, CERM, 10 pF, 50 V,+/- 5%, C0G/NP0, 0402; Manufacturer: Walsin; Alternate PartNumber: GRM1555C1H100JA01D; Polarized: N; Value: 10pF; U/M: EA; VDC_V: 50V; TaMin_C: -55°C; TaMax_C: 125°C; Cap_Case: 0402; SizeAreaWB_mm2: 3; SizeZ_mm: 0.6; SizeX_mm: 1; SizeY_mm: 0.5; AEC Category: Q200
C31 C33 = CMP-0085844-1: CAP, CERM, 6.2 pF, 50 V,+/- 4%, C0G/NP0, 0402; Manufacturer: Walsin; Alternate PartNumber: GRM1555C1H6R2CA01D; Polarized: N; Value: 6.2pF; U/M: EA; VDC_V: 50V; TaMin_C: -55°C; TaMax_C: 125°C; Cap_Case: 0402; SizeAreaWB_mm2: 3; SizeZ_mm: 0.6; SizeX_mm: 1; SizeY_mm: 0.5; AEC Category: Q200
C32 = CMP-0085407-1: CAP, CERM, 0.6pF, 25 V,+/- 16%, C0G/NP0, 0201; Manufacturer: MuRata; Polarized: N; CompType: Capacitor; U/M: EA; VDC_V: 25V; TaMin_C: -55°C; TaMax_C: 125°C; Cap_Case: 0201; SizeArea_mm2: 0.18; SizeAreaWB_mm2: 2.08; SizeX_mm: 0.6; SizeY_mm: 0.3; SizeZ_mm: 0.33; AEC Category: Q200
J10 = CMP-0054802-2: Header, 2.54mm, 3x2, Gold, TH; Manufacturer: Wurth Elektronik; Green_Lifecycle: Active; Shrouded: N; Gender: Male; Green_REACh: Passed; Row_Count: 2; RowSpacing_mm: 2.54
L3 L5 = CMP-0058761-1: Inductor, Multilayer, Ferrite, 2.2 uH, 1.2 A, 0.11 ohm, SMD; PartNumber: LQM2MPN2R2NG0; Manufacturer: MuRata; Alternate PartNumber: ----; Value: 2.2uH; Ind_H: 2.2µH; Imax_A: 1.2A; Irms: 1.2A @ 40C rise; DCR_ohm: 1.1d; SizeAreaWB_mm2: 7.8; SizeArea_mm2: 3.2; SizeX_mm: 2; SizeY_mm: 1.6; SizeZ_mm: 1; AEC Category: Q200; AEC Qualified: N
L4 = CMP-0058750-1: Inductor, Multilayer, Ferrite, 1 uH, 1.6 A, 0.055 ohm, SMD; PartNumber: LQM2HPN1R0MG0L; Manufacturer: MuRata; Alternate PartNumber: ----; Value: 1uH; Ind_H: 1µH; Imax_A: 1.6A; Irms: 1.6A @ 40C rise; DCR_ohm: 0.055; Green_Lifecycle: Active; SizeAreaWB_mm2: 10.5; Green_REACh: Passed; SizeZ_mm: 1.2; SizeX_mm: 2.5; SizeY_mm: 2; SizeArea_mm2: 5; AEC Category: Q200
L6 = CMP-0062710-1: Inductor, Multilayer, Ferrite, 10 uH, 0.7 A, 0.364 ohm, SMD; PartNumber: MLP2520S100MT0S1; Manufacturer: TDK; Alternate PartNumber: ----; Value: 10uH; Ind_H: 10µH; Imax_A: 7dA; Irms: 0.7A @ 40C rise; DCR_ohm: 3.64d; Value2: 0.7A; SizeAreaWB_mm2: 11.84; SizeArea_mm2: 5.94; SizeX_mm: 2.7; SizeY_mm: 2.2; SizeZ_mm: 1; AEC Category: Q200; AEC Qualified: N
R19 R21 R27 R28 = CMP-0027008-4: RES, 0, 5%, 0.05 W, 0201; Manufacturer: Vishay-Dale; Power_W: 50mW; TempCo: ppm/C; Value_Code: 0000; Value: 0; EIA_Code: E24; SizeX_mm: 0.6; SizeY_mm: 0.3; SizeZ_mm: 0.26; Value2: 0.05W; SizeArea_mm2: 0.18; CompType: Resistor; AEC Qualified: N; AEC Category: Q200
R20 R30 R31 = CMP-0026823-3: RES, 100 k, 5%, 0.063 W, AEC-Q200 Grade 0, 0402; Manufacturer: Vishay-Dale; Power_W: 63mW; TempCo: 200 ppm/C; Value: 100k; EIA_Code: E24; SizeX_mm: 1; SizeY_mm: 0.5; SizeZ_mm: 0.6; Value2: 0.063W; AEC Qualified: Y; VDC_V: 50V; AEC Category: Q200; AEC Grade: 0
R22-R26 = CMP-0027184-1: as R8 on sheet CC3230x-CC26x2EM-7ID_Power_Reset_Interfaces
R29 = CMP-0026886-3: RES, 270, 5%, 0.063 W, AEC-Q200 Grade 0, 0402; Manufacturer: Vishay-Dale; Power_W: 63mW; TempCo: 200 ppm/C; Value_Code: 270R; Value: 270; EIA_Code: E24; SizeX_mm: 1; SizeY_mm: 0.5; SizeZ_mm: 0.6; Value2: 0.063W; AEC Qualified: Y; VDC_V: 50V; AEC Category: Q200; AEC Grade: 0
R32 = CMP-0026892-5: RES, 2.7 k, 5%, 0.063 W, AEC-Q200 Grade 0, 0402; Manufacturer: Vishay-Dale; Power_W: 63mW; TempCo: 200 ppm/C; Value_Code: 2k70; Value: 2.7k; EIA_Code: E24; SizeX_mm: 1; SizeY_mm: 0.5; SizeZ_mm: 0.6; Value2: 0.063W; AEC Qualified: Y; VDC_V: 50V; AEC Category: Q200; AEC Grade: 0
U2 = CMP-0086651-1: FLASH - NOR Memory IC 32Mb (4M x 8) SPI 80MHz 8-USON (4x3); Manufacturer: Macronix; SizeZ_mm: 0.6mm
U3 = CMP-0084310-2: SimpleLink Wi-Fi, Single-Chip Wireless MCU Solution, RGK0064B (VQFN-64); Manufacturer: Texas Instruments; AEC Qualified: N; SizeX_mm: 9; AEC Category: Q200; CompType: IC; SizeZ_mm: 1; SizeAreaWB_mm2: 121; SizeArea_mm2: 81
Y1 = CMP-0004575-3: CRYSTAL, 32.768KHz, 9PF, SMD; PartNumber: ABS07-32.768KHZ-9-T; Manufacturer: Abracon Corporation; Alternate Manufacturer: ----; TaMin_C: -40°C; TaMax_C: 85°C; Frequency Stability: +/-20ppm
Y2 = CMP-0077111-2: Crystal, 40 MHz, 8 pF, SMD; Manufacturer: TXC Corporation; Alternate Manufacturer: ----; Alternate PartNumber: Order Directly from TXC; TaMax_C: 95°C; TaMin_C: -40°C; U/M: EA; Frequency Stability: ±15ppm

## Sheet CC3230x-CC26x2EM-7ID_CC26x2R_EngineArea.SchDoc
size 558 x 431 mm; Date: Not shown in title block; ApprovedBy: Not shown in title block; CheckedBy: Not shown in title block; Author: Not shown in title block; CompanyName: Not shown in title block; Engineer: Not shown in title block; Organization: Not shown in title block; Address1: Not shown in title block; Address2: Not shown in title block; Address3: Not shown in title block; Address4: Not shown in title block; DocumentNumber: 3; Revision: Use project parameter SCH_Rev; SheetNumber: 3; SheetTotal: 5; PageSetup: Record=PageOptions¦CenterHorizontal=True¦CenterVertical=True¦PrintScale=1.00¦XCorrection=1.00¦YCorrection=1.00¦PrintKind=0¦BorderSize=5000000¦LeftOffset=0¦BottomOffset=0¦Orientation=2¦PaperLength=1000¦PaperWidth=1000¦Scale=100¦PaperSource=15¦PrintQuality=600¦MediaType=1¦DitherType=10¦PaperKind=Letter¦PrintScaleMode=1
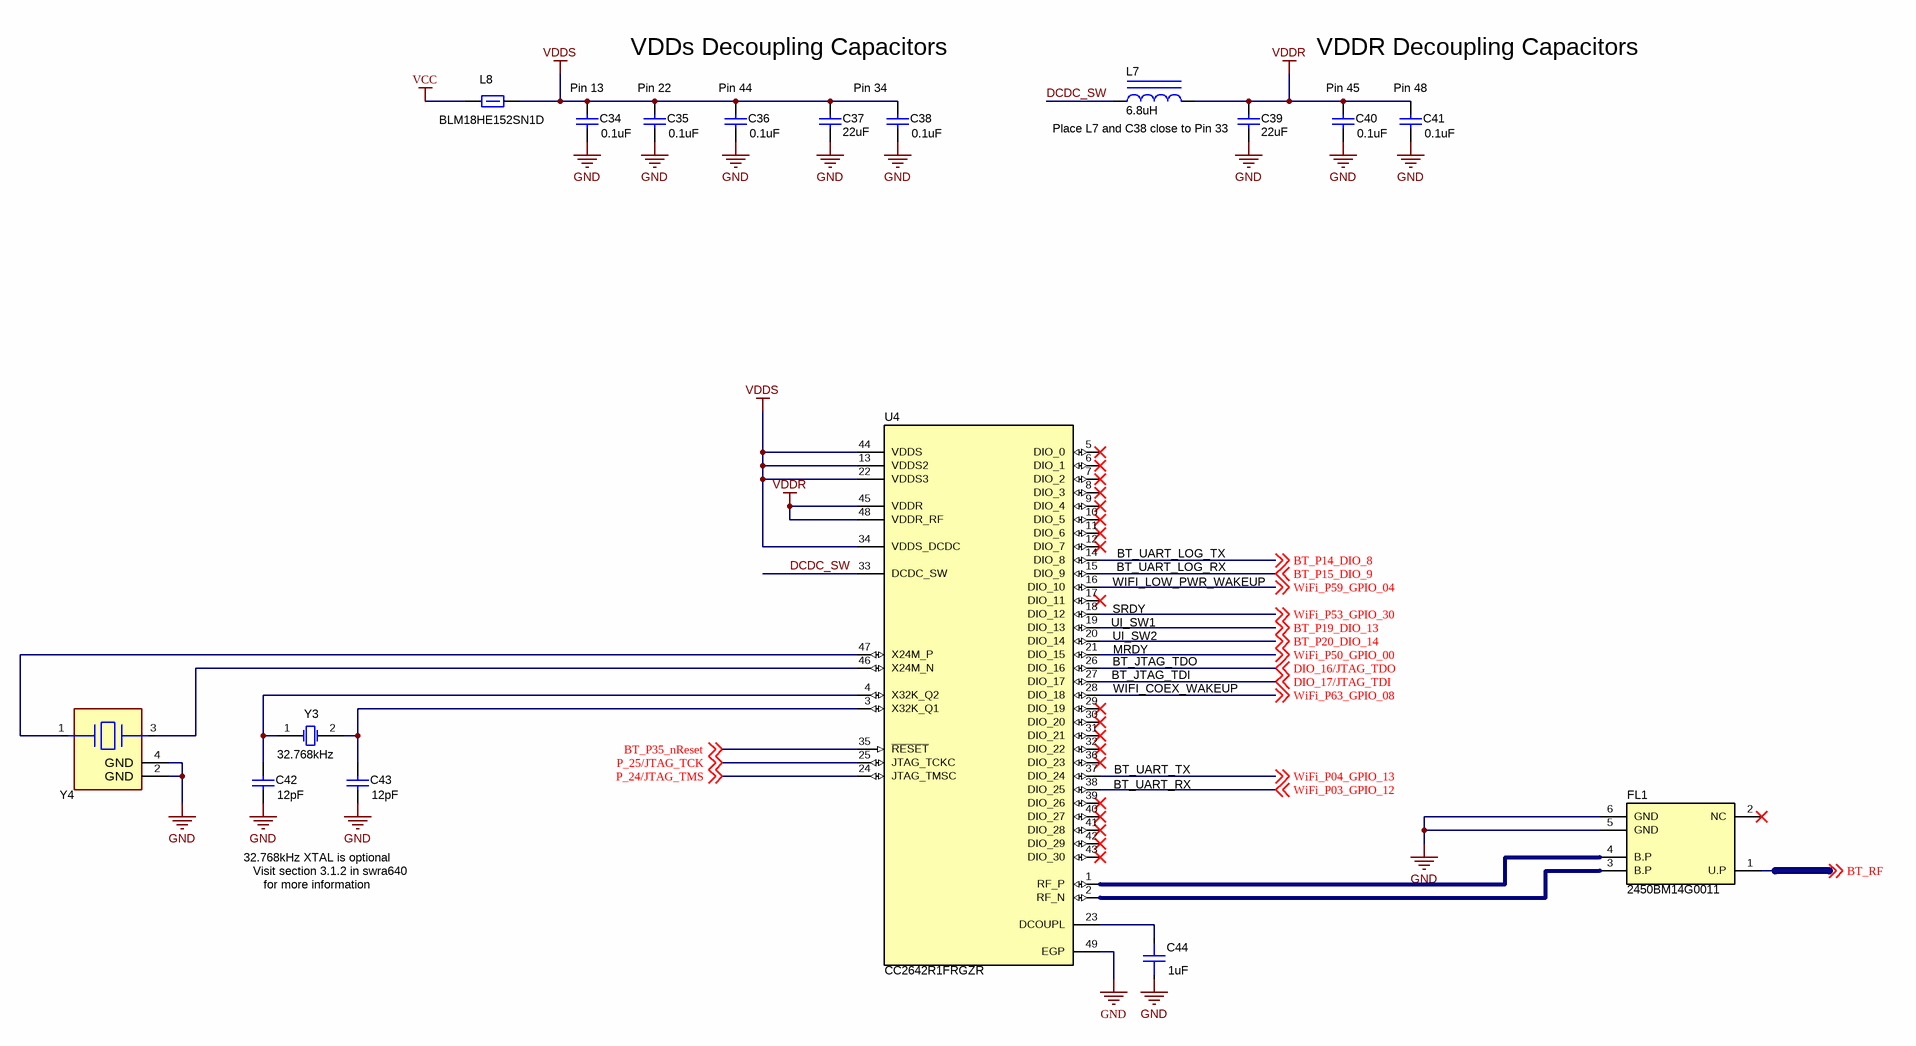
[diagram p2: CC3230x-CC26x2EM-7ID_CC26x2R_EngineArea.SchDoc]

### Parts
C34  ValueDisplayed: 0.1uF  [0201]  (hidden comment: GRM033Z71C104KE14D)
C35  ValueDisplayed: 0.1uF  [0201]  (hidden comment: GRM033Z71C104KE14D)
C36  ValueDisplayed: 0.1uF  [0201]  (hidden comment: GRM033Z71C104KE14D)
C37  ValueDisplayed: 22uF  [0402]  (hidden comment: GRM155R60J226ME11D)
C38  ValueDisplayed: 0.1uF  [0201]  (hidden comment: GRM033Z71C104KE14D)
C39  ValueDisplayed: 22uF  [0402]  (hidden comment: GRM155R60J226ME11D)
C40  ValueDisplayed: 0.1uF  [0201]  (hidden comment: GRM033Z71C104KE14D)
C41  ValueDisplayed: 0.1uF  [0201]  (hidden comment: GRM033Z71C104KE14D)
C42  ValueDisplayed: 12pF  [0201_033]  (hidden comment: C0603C0G1E120J030BA)
C43  ValueDisplayed: 12pF  [0201_033]  (hidden comment: C0603C0G1E120J030BA)
C44  ValueDisplayed: 1uF  [FP-JMK063BC6105MP-F_0201-MFG]  (hidden comment: JMK063BC6105MP-F)
FL1  2450BM14G0011  [Johanson_2450BM14G0011]
L7  ValueDisplayed: 6.8uH  [0805_HV]  (hidden comment: MLZ2012N6R8LT000)
L8  BLM18HE152SN1D  [0603]
U4  CC2642R1FRGZR  [RGZ0048A]
Y3  Frequency_Fixed: 32.768kHz  [Epson_FC-135]  (hidden comment: FC-135 32.7680KA-AG0)
Y4  CX2016DB48000C0WPLA2  [FP-CX2016DB48000C0WPLA2_SMD4-MFG]  (value not drawn)

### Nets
GND: C34.2 C35.2 C36.2 C37.2 C38.2 C39.2 C40.2 C41.2 C42.2 C43.2 C44.1 FL1.5(GND) FL1.6(GND) U4.49(EGP) Y4.2(GND) Y4.4(GND)
VCC: L8.1
VDDR: C39.1 C40.1 C41.1 L7.2 U4.45(VDDR) U4.48(VDDR_RF)
VDDS: C34.1 C35.1 C36.1 C37.1 C38.1 L8.2 U4.13(VDDS2) U4.22(VDDS3) U4.34(VDDS_DCDC) U4.44(VDDS)
BT_P14_DIO_8: U4.14(DIO_8) ; off-sheet BT_P14_DIO_8
BT_P15_DIO_9: U4.15(DIO_9) ; off-sheet BT_P15_DIO_9
BT_P19_DIO_13: U4.19(DIO_13) ; off-sheet BT_P19_DIO_13
BT_P20_DIO_14: U4.20(DIO_14) ; off-sheet BT_P20_DIO_14
BT_P35_nReset: U4.35(~{RESET}) ; off-sheet BT_P35_nReset
BT_RF: FL1.1(U.P) ; off-sheet BT_RF
DCDC_SW: L7.1 U4.33(DCDC_SW)
DIO_16/JTAG_TDO: U4.26(DIO_16) ; off-sheet DIO_16/JTAG_TDO
DIO_17/JTAG_TDI: U4.27(DIO_17) ; off-sheet DIO_17/JTAG_TDI
P_24/JTAG_TMS: U4.24(JTAG_TMSC) ; off-sheet P_24/JTAG_TMS
P_25/JTAG_TCK: U4.25(JTAG_TCKC) ; off-sheet P_25/JTAG_TCK
WiFi_P03_GPIO_12: U4.38(DIO_25) ; off-sheet WiFi_P03_GPIO_12
WiFi_P04_GPIO_13: U4.37(DIO_24) ; off-sheet WiFi_P04_GPIO_13
WiFi_P50_GPIO_00: U4.21(DIO_15) ; off-sheet WiFi_P50_GPIO_00
WiFi_P53_GPIO_30: U4.18(DIO_12) ; off-sheet WiFi_P53_GPIO_30
WiFi_P59_GPIO_04: U4.16(DIO_10) ; off-sheet WiFi_P59_GPIO_04
WiFi_P63_GPIO_08: U4.28(DIO_18) ; off-sheet WiFi_P63_GPIO_08
NetC42_1: C42.1 U4.4(X32K_Q2) Y3.1(OSC1)
NetC43_1: C43.1 U4.3(X32K_Q1) Y3.2(OSC2)
NetC44_2: C44.2 U4.23(DCOUPL)
NetFL1_3: FL1.3(B.P) U4.2(RF_N)
NetFL1_4: FL1.4(B.P) U4.1(RF_P)
NetU4_46: U4.46(X24M_N) Y4.3(2_HOT)
NetU4_47: U4.47(X24M_P) Y4.1(1_HOT)

Not connected (* = marked no-connect by the designer): FL1 2(NC)*; U4 5(DIO_0)* 6(DIO_1)* 7(DIO_2)* 8(DIO_3)* 9(DIO_4)* 10(DIO_5)* 11(DIO_6)* 12(DIO_7)* 17(DIO_11)* 29(DIO_19)* 30(DIO_20)* 31(DIO_21)* 32(DIO_22)* 36(DIO_23)* 39(DIO_26)* 40(DIO_27)* 41(DIO_28)* 42(DIO_29)* 43(DIO_30)*

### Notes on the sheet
- (near C34) Pin 13
- (near C35) Pin 22
- (near C36) Pin 44
- VDDs Decoupling Capacitors
- Pin 34
- (near C40) Pin 45
- (near C41) Pin 48
- VDDR Decoupling Capacitors
- Place L7 and C38 close to Pin 33
- BT_UART_LOG_TX
- BT_UART_LOG_RX
- (near U4) SRDY
- (near U4) UI_SW1
- (near U4) UI_SW2
- WIFI_LOW_PWR_WAKEUP
- (near U4) MRDY
- (near U4) BT_JTAG_TDI
- (near U4) BT_JTAG_TDO
- WIFI_COEX_WAKEUP
- (near U4) BT_UART_TX
- (near U4) BT_UART_RX
- 32.768kHz XTAL is optional
- for more information
- Visit section 3.1.2 in swra640

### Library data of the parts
C34-C36 C38 C40 C41 = CMP-0064970-1: as C5 on sheet CC3230x-CC26x2EM-7ID_Power_Reset_Interfaces
C37 C39 = CMP-0006545-2: CAP, CERM, 22 uF, 6.3 V, +/- 20%, X5R, 0402; Manufacturer: MuRata; TaMin_C: -55°C; Polarized: N; SizeAreaWB_mm2: 3; Value1: Unknown; U/M: EA; Value: 22uF; TaMax_C: 85°C; SizeZ_mm: 0.6; SizeY_mm: 0.5; Value2: 6.3V; CompType: Capacitor; SizeX_mm: 1; Cap_F: 22µF; AEC Category: Q200
C42 C43 = CMP-0009633-3: CAP, CERM, 12 pF, 25 V, +/- 5%, C0G/NP0, 0201; Manufacturer: TDK; TaMin_C: -55°C; ESR_ohm: 0; Polarized: N; SizeAreaWB_mm2: 2.08; Value1: 0 ohm; U/M: EA; Value: 12pF; TaMax_C: 125°C; SizeZ_mm: 0.33; SizeX_mm: 0.6; SizeY_mm: 0.3; Cap_Case: 0201; Value2: 25V; SizeArea_mm2: 0.18; CompType: Capacitor; IRMS_A: 0A; AEC Category: Q200
C44 = CMP-0089441-1: 1µF ±20% 6.3V Ceramic Capacitor X6S 0201 (0603 Metric); Manufacturer: Taiyo Yuden; AEC Qualified: No; TempCo: 22%; SizeZ_mm: 0.39mm
FL1 = CMP-0001890-2: 2.4GHz Impedance Matched Balun + embedded FCC/ETSI Band Pass Filter, SMD; Manufacturer: Johanson Technology; SizeZ_mm: 0.7; SizeX_mm: 1.6; SizeY_mm: 0.8; SizeAreaWB_mm2: 4.68; SizeArea_mm2: 1.28
L7 = CMP-0062727-1: Inductor, Multilayer, Ferrite, 6.8 uH, 0.11 A, 0.25 ohm, SMD; Manufacturer: TDK; Isat: 0.11A @ 50% inductance drop; Irms: 0.55A @ 20C rise; Green_Lifecycle: Active; SizeAreaWB_mm2: 6.75; DCR_ohm: 2.5d; Green_REACh: Passed; Value: 6.8uH; Imax_A: 1.1dA; SizeZ_mm: 1.45; SizeX_mm: 2; SizeY_mm: 1.25; Value2: 0.11A; SizeArea_mm2: 2.5; Ind_H: 6.8µH; AEC Category: Q200
L8 = CMP-0003349-2: Ferrite Bead, 1500 ohm @ 100 MHz, 0.5 A, 0603; Manufacturer: MuRata; Ztyp@1GHz_Ohm: 1.5k; SizeAreaWB_mm2: 4.68; DCR_ohm: 5d; Value1: 0.5 ohm; Imax_A: 5dA; SizeZ_mm: 1; SizeX_mm: 1.6; SizeY_mm: 0.8; Value2: 0.5A; SizeArea_mm2: 1.28
U4 = CMP-0083675-2: SimpleLink(TM) Bluetooth(R) 5 low energy Wireless MCU, RGZ0048A (VQFN-48); Alternate Manufacturer: Texas Instruments; Alternate PartNumber: CC2642R1FRGZT; SizeZ_mm: 1; AEC Category: Q200; SizeY_mm: 7; Rating: #N/A; SizeAreaWB_mm2: 81; AEC Qualified: N; CompType: IC; SizeArea_mm2: 49
Y3 = CMP-0079303-1: Crystal, 32.768 KHz, 20 ppm, 7 pF, SMD; Manufacturer: Epson; TaMin_C: -40°C; Frequency Tolerance: 20 ppm; Load Capacitance: 7 pF; TaMax_C: 85°C; AEC Qualified: N; AEC Category: Q200
Y4 = CMP-0088076-1: 48MHz ±20ppm Crystal 7pF 50 Ohms 4-SMD, No Lead; Manufacturer: Kyocera; Symbol Name: SYM-CX2016DB48000C0WPLA2; SizeZ_mm: 0.45mm

## Sheet CC3230x-CC26x2EM-7ID_AntennaRFSection.SchDoc
size 558 x 431 mm; Date: Not shown in title block; ApprovedBy: Not shown in title block; CheckedBy: Not shown in title block; Author: Not shown in title block; CompanyName: Not shown in title block; Engineer: Not shown in title block; Organization: Not shown in title block; Address1: Not shown in title block; Address2: Not shown in title block; Address3: Not shown in title block; Address4: Not shown in title block; DocumentNumber: 4; Revision: Use project parameter SCH_Rev; SheetNumber: 4; SheetTotal: 5; PageSetup: Record=PageOptions¦CenterHorizontal=True¦CenterVertical=True¦PrintScale=1.00¦XCorrection=1.00¦YCorrection=1.00¦PrintKind=0¦BorderSize=5000000¦LeftOffset=0¦BottomOffset=0¦Orientation=2¦PaperLength=1000¦PaperWidth=1000¦Scale=100¦PaperSource=15¦PrintQuality=600¦MediaType=1¦DitherType=10¦PaperKind=Letter¦PrintScaleMode=1
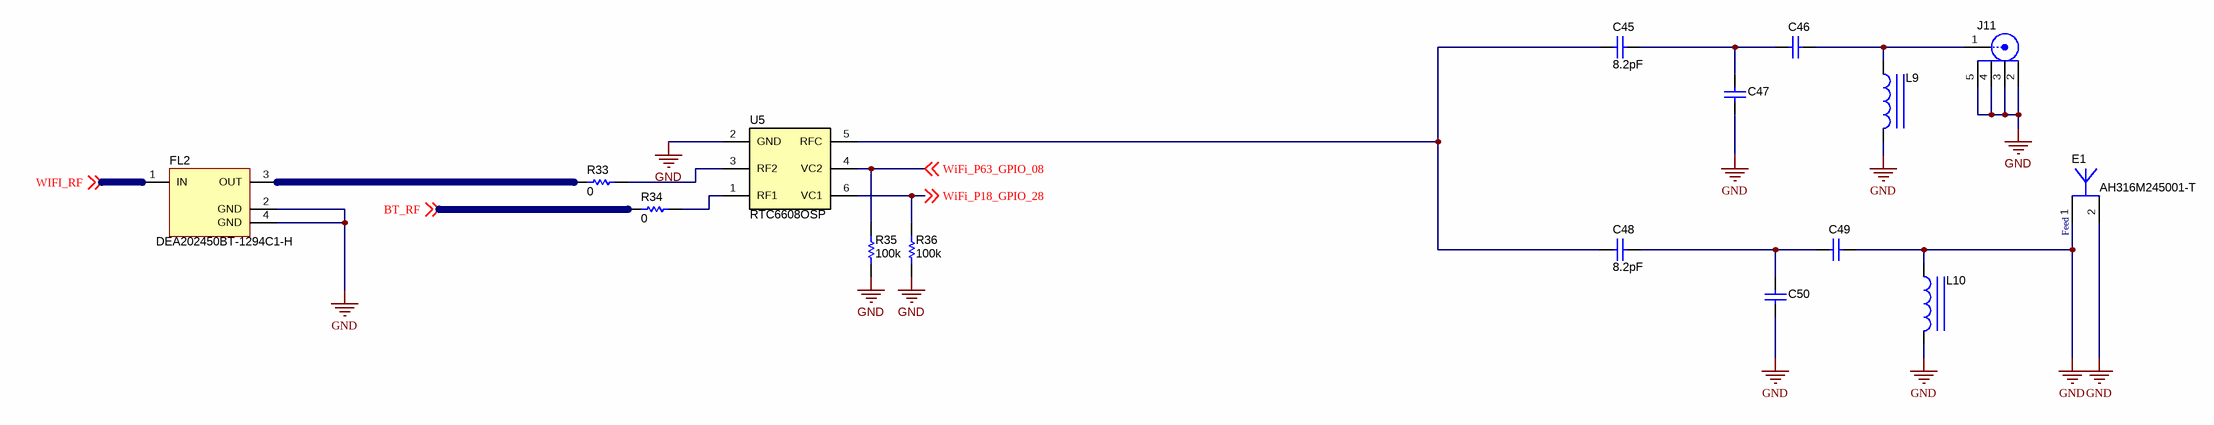
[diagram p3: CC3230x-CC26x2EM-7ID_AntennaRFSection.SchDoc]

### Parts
C45  ValueDisplayed: 8.2pF  [0402S]  (hidden comment: CMP-0006495-2)
C46  CMP-0006447-2  [0402L]  (value not drawn)
C47  CMP-0006426-2  [0402S]  (value not drawn)
C48  ValueDisplayed: 8.2pF  [0402S]  (hidden comment: CMP-0006495-2)
C49  CMP-0006447-2  [0402L]  (value not drawn)
C50  CMP-0006426-2  [0402S]  (value not drawn)
E1  AH316M245001-T  [TAYO_AH316M]
FL2  PartNumber: DEA202450BT-1294C1-H  [TDK_DEA202450BT-1294C1-H]  (hidden comment: CMP-0002039-2)
J11  CMP-0055832-1  [Hustsan_SMA-10V21-TGG]  (value not drawn)
L9  LQG15HS3N9S02D  [IND_LQG15H]  (value not drawn)
L10  LQG15HS3N9S02D  [IND_LQG15H]  (value not drawn)
R33  ValueDisplayed: 0  [0201]  (hidden comment: ERJ-1GE0R00C)
R34  ValueDisplayed: 0  [0201]  (hidden comment: ERJ-1GE0R00C)
R35  ValueDisplayed: 100k  [0201]  (hidden comment: RC0201JR-7D100KL)
R36  ValueDisplayed: 100k  [0201]  (hidden comment: RC0201JR-7D100KL)
U5  RTC6608OSP  [Richwave_RTC6608OSP]

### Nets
GND: C47.2 C49.2 C50.2 E1.1 E1.2 FL2.2(GND) FL2.4(GND) J11.2 J11.3 J11.4 J11.5 L9.2 L10.1 L10.2 R35.1 R36.1 U5.2(GND)
BT_RF: R34.2 ; off-sheet BT_RF
WiFi_P18_GPIO_28: R36.2 U5.6(VC1) ; off-sheet WiFi_P18_GPIO_28
WiFi_P63_GPIO_08: R35.2 U5.4(VC2) ; off-sheet WiFi_P63_GPIO_08
WIFI_RF: FL2.1(IN) ; off-sheet WIFI_RF
NetC45_1: C45.1 C48.1 U5.5(RFC)
NetC45_2: C45.2 C46.1 C47.1
NetC46_2: C46.2 J11.1 L9.1
NetC48_2: C48.2 C49.1 C50.1
NetFL2_3: FL2.3(OUT) R33.2
NetR33_1: R33.1 U5.3(RF2)
NetR34_1: R34.1 U5.1(RF1)

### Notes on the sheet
- (near E1) Feed

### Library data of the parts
C45 C48 = CMP-0006495-2: CAP, CERM, 8.2 pF, 50 V, +/- 5%, C0G/NP0, 0402; PartNumber: GRM1555C1H8R2CA01D; Manufacturer: MuRata; Alternate PartNumber: 0402N8R2C500CT; Alternate Manufacturer: Walsin; Polarized: N; CompType: Capacitor; Value: 8.2pF; U/M: EA; Value1: Unknown; VDC_V: 50V; TaMin_C: -55°C; TaMax_C: 125°C; Cap_Case: 0402; SizeArea_mm2: 0.5; SizeAreaWB_mm2: 3; SizeX_mm: 1; SizeZ_mm: 0.6; AEC Category: Q200
C46 C49 = CMP-0006447-2: CAP, CERM, 2.2 pF, 50 V, +/- 5%, C0G/NP0, 0402; PartNumber: GRM1555C1H2R2BA01D; Manufacturer: MuRata; Alternate PartNumber: ----; Polarized: N; CompType: Capacitor; Value: 2.2pF; U/M: EA; Value1: Unknown; VDC_V: 50V; TaMin_C: -55°C; TaMax_C: 125°C; Cap_Case: 0402; SizeArea_mm2: 0.5; SizeAreaWB_mm2: 3; SizeX_mm: 1; SizeZ_mm: 0.6; AEC Category: Q200
C47 C50 = CMP-0006426-2: CAP, CERM, 1 pF, 50 V, +/- 10%, C0G/NP0, 0402; PartNumber: GRM1555C1H1R0BA01D; Manufacturer: MuRata; Alternate PartNumber: ----; Polarized: N; CompType: Capacitor; Value: 1pF; U/M: EA; Value1: Unknown; VDC_V: 50V; TaMin_C: -55°C; TaMax_C: 125°C; Cap_Case: 0402; SizeAreaWB_mm2: 3; SizeZ_mm: 0.6; SizeX_mm: 1; SizeY_mm: 0.5; AEC Category: Q200
E1 = CMP-0002031-2: ANT BLUETOOTH W-LAN ZIGBEE WIMAX, SMD; Manufacturer: Taiyo Yuden; CompType: Antenna
FL2 = CMP-0002039-2: Multilayer Chip Band Pass Filter For 2.4GHz W-LAN/Bluetooth, SMD; Manufacturer: TDK; Alternate Manufacturer: ----; Value: 1.02 dB
J11 = CMP-0055832-1: Connector, SMA, Vertical, Gold, SMT; PartNumber: SMA-10V21-TGG; Manufacturer: Hus-Tsan Group Co., Ltd.; Alternate Manufacturer: 傲创; Alternate PartNumber: SMA-050710; CT: TRUE; CNHeader: FALSE
L9 L10 = CMP-0058633-2: Inductor, Multilayer, Air Core, 3.9 nH, 0.75 A, 0.14 ohm, SMD; Manufacturer: MuRata; Irms: 0.75A @ 25C rise; Green_Lifecycle: Active; SizeAreaWB_mm2: 3; DCR_ohm: 1.4d; Green_REACh: Passed; Value: 3.9nH; Imax_A: 7.5dA; SizeZ_mm: 0.55; SizeX_mm: 1; SizeY_mm: 0.5; Value2: 0.75A; AEC Qualified: N; AEC Category: Q200
R33 R34 = CMP-0027011-3: RES, 0, 5%, 0.05 W, 0201; Manufacturer: Panasonic; Alternate Manufacturer: Vishay-Dale; Alternate PartNumber: CRCW02010000Z0ED; CompType: Resistor; Value: 0; Value_Code: 0000; Power_W: 50mW; Value2: 0.05W; VDC_V: 15V; TempCo: 600 ppm/C; SizeArea_mm2: 0.18; SizeX_mm: 0.6; SizeY_mm: 0.3; SizeZ_mm: 0.26; EIA_Code: E24; U/M: EA; AEC Category: Q200
R35 R36 = CMP-0027184-1: as R8 on sheet CC3230x-CC26x2EM-7ID_Power_Reset_Interfaces
U5 = CMP-0065464-1: 0.03 GHz-6 GHz SPDT Switch; Manufacturer: Richwave; Alternate Manufacturer: ----; SizeAreaWB_mm2: 4.0; SizeArea_mm2: 1.0; SizeZ_mm: 0.4

## Sheet CC3230x-CC26x2EM-7ID_Hardware.SchDoc
size 558 x 431 mm; Date: Not shown in title block; ApprovedBy: Not shown in title block; CheckedBy: Not shown in title block; Author: Not shown in title block; CompanyName: Not shown in title block; Engineer: Not shown in title block; Organization: Not shown in title block; Address1: Not shown in title block; Address2: Not shown in title block; Address3: Not shown in title block; Address4: Not shown in title block; DocumentNumber: 5; Revision: Use project parameter SCH_Rev; SheetNumber: 5; SheetTotal: 5; PageSetup: Record=PageOptions¦CenterHorizontal=True¦CenterVertical=True¦PrintScale=1.00¦XCorrection=1.00¦YCorrection=1.00¦PrintKind=0¦BorderSize=5000000¦LeftOffset=0¦BottomOffset=0¦Orientation=2¦PaperLength=1000¦PaperWidth=1000¦Scale=100¦PaperSource=15¦PrintQuality=600¦MediaType=1¦DitherType=10¦PaperKind=Letter¦PrintScaleMode=1
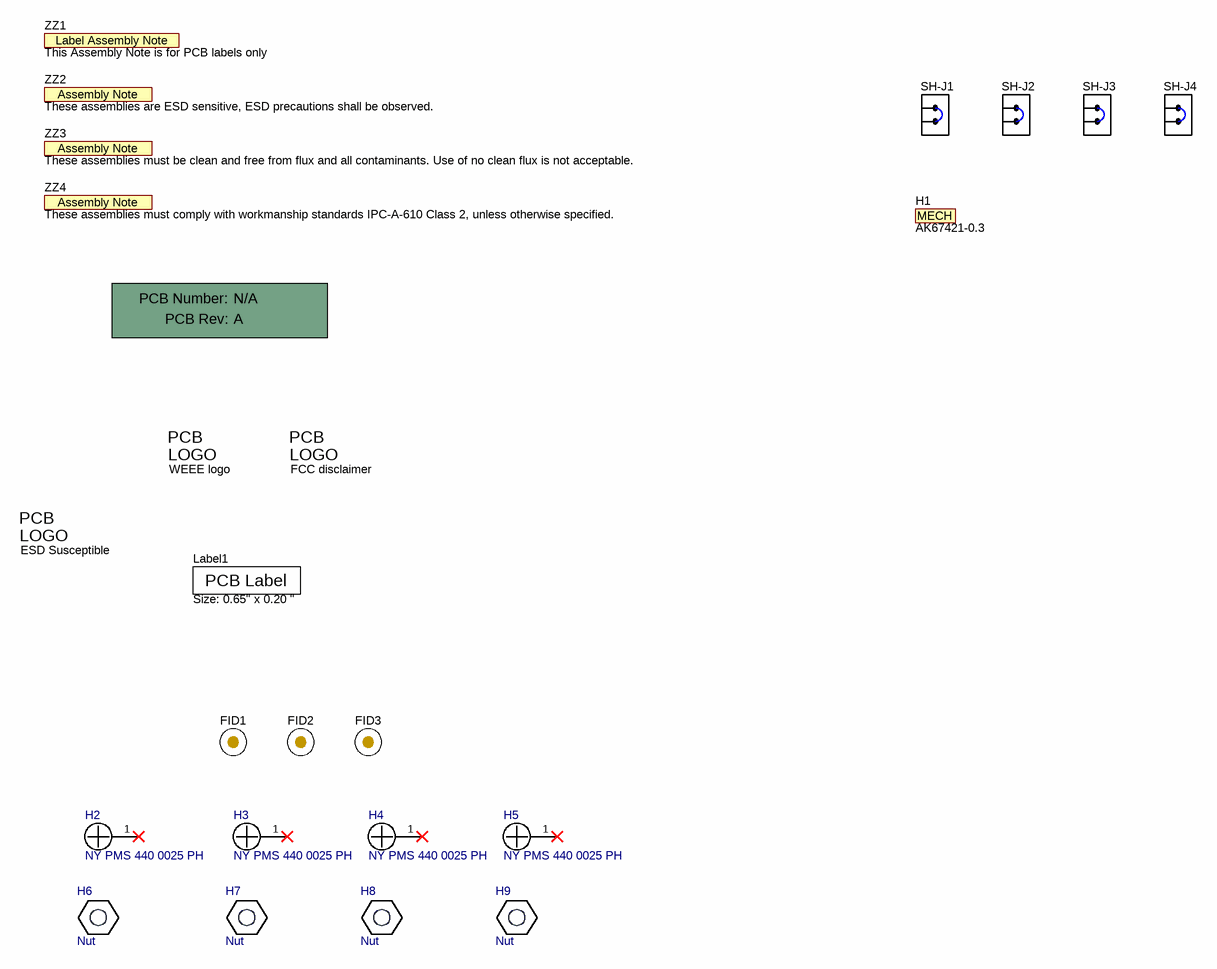
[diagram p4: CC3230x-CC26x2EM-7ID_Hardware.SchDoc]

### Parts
FID1  CMP-0077181-1  [Fiducial10-20]  (value not drawn)  (no BOM)
FID2  CMP-0077181-1  [Fiducial10-20]  (value not drawn)  (no BOM)
FID3  CMP-0077181-1  [Fiducial10-20]  (value not drawn)  (no BOM)
H1  AK67421-0.3  (mechanical)
H2  NY PMS 440 0025 PH  [NY PMS 440 0025 PH]
H3  NY PMS 440 0025 PH  [NY PMS 440 0025 PH]
H4  NY PMS 440 0025 PH  [NY PMS 440 0025 PH]
H5  NY PMS 440 0025 PH  [NY PMS 440 0025 PH]
H6  Nut  [Keystone_1902C]
H7  Nut  [Keystone_1902C]
H8  Nut  [Keystone_1902C]
H9  Nut  [Keystone_1902C]
Label1  Note: Size: 0.65" x 0.20 "  [Label_650x200]  (hidden comment: CMP-0003625-1)
Logo2  WEEE logo  [WEEE_Minimum]  (no BOM)
Logo3  FCC disclaimer  [FCC_disclaimer_stacked]  (no BOM)
Logo4  ESD Susceptible  [ESD_Overlay_Medium]  (no BOM)
PCB1  Printed Circuit Board  (value not drawn)  (mechanical)
SH-J1  60900213421  [Wurth_60900213421]  (value not drawn)
SH-J2  60900213421  [Wurth_60900213421]  (value not drawn)
SH-J3  60900213421  [Wurth_60900213421]  (value not drawn)
SH-J4  60900213421  [Wurth_60900213421]  (value not drawn)
ZZ1  This Assembly Note is for PCB labels only  [AssemblyNoteLabel]  (no BOM)
ZZ2  These assemblies are ESD sensitive, ESD precautions shall be observed.  [AssemblyNote]  (no BOM)
ZZ3  These assemblies must be clean and free from flux and all contaminants. Use of no clean flux is not acceptable.  [AssemblyNote]  (no BOM)
ZZ4  These assemblies must comply with workmanship standards IPC-A-610 Class 2, unless otherwise specified.  [AssemblyNote]  (no BOM)

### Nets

Not connected (* = marked no-connect by the designer): H2 1*; H3 1*; H4 1*; H5 1*

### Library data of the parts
FID1-FID3 = CMP-0077181-1: Fiducial mark.  There is nothing to buy or mount.
H1 = CMP-0077983-1: Cable, USB-A to micro USB-B, 0.3 m; Manufacturer: Assman WSW
H2-H5 = CMP-0003617-1: Machine Screw, Round, #4-40 x 1/4, Nylon, Philips panhead; Manufacturer: B&F Fastener Supply; CompType: Hardware
H6-H9 = CMP-0003610-1: Standoff, Hex, 0.5"L #4-40 Nylon; Manufacturer: Keystone; PartNumber: 1902C; CompType: Hardware
Label1 = CMP-0003625-1: Thermal Transfer Printable Labels, 0.650" W x 0.200" H - 10,000 per roll; Manufacturer: Brady; PartNumber: THT-14-423-10; Alternate Manufacturer: ----; CompType: Label
Logo2 = CMP-0074769-1
Logo3 = CMP-0074847-1: FCC_disclaimer; Library Reference: Logo
Logo4 = CMP-0074840-1: ESD Susceptible Symbol; SymbolCreator: a0412235; Library Reference: Logo; Lib Reference: ESD_Susceptible
PCB1 = CMP-0003618-2: Manufacturer: Any; Alternate Manufacturer: ----; CompType: PCB
SH-J1-SH-J4 = CMP-0003761-2: Shunt, 2.54mm, Gold, Black; Manufacturer: Wurth Elektronik
ZZ1 = CMP-0003616-3
ZZ2 = CMP-0077236-1
ZZ3 = CMP-0077237-1
ZZ4 = CMP-0077238-1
